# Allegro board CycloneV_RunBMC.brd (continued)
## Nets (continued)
P3V3_AUX_M10_VCCIO1A: CB86.1 CB88.1 CB97.1 FBB2.2(B) UT4.G4 UT4.H4
P3V3_AUX_SPI: CB14.1 CB18.1 CRB1.1(C) EUB1.8 RB18.1 RB29.1 RB35.1 RB38.1 TP1.1(TP)
P3V3_SI5338_AUX: C5C1.1 C5C2.1 C5C7.1 C5C8.1 C5C13.1 C5N17.1 CB199.1 CB201.1 CB209.1 CB212.1 EU5C1.10 EU5C1.11 EU5C1.14 EU5C1.18 EU5C1.20 FB5C1.2(B)
P3V3_USBPHY_AUX: C2L16.1 C2L17.1 C2L18.1 R2L48.2(B) R8A64.1 U8A6.8 U8A6.11 U8A6.14 U8A6.32
P3V3_USBPHY_OUT_AUX: C7A14.1 C7A15.1 U8A6.20
P3V3_USBPHY_USB2B_AUX: C316.1 C317.1 C318.1 EU12.8 EU12.11 EU12.14 EU12.32 R410.1 R414.2(B)
P3V3_USBPHY_USB2B_OUT_AUX: C319.1 C320.1 EU12.20
P5V_AUX: FB11.1 R391.2(B) R392.1
P5V_AUX_PIN140: JT3.140 R391.1
P5V_AUX_USB2A_VSENSE: JT3.211 R392.2(B)
P5V_USBPHY_AUX: C3L11.1 CB206.1 CB207.1 FB11.2(B) R7A52.1
P5V_USBPHY_USB2B_AUX: C305.1 C321.1 C322.1 FB17.2(B) R395.1
P5V_USBPHY_USB2B_VSENSE: FB17.1 JT3.209
P12V_AUX: FBB7.1 FBB11.1 RB171.1 RT116.2(B)
P12V_AUX_EDGE: JT3.1 RT116.1 RT134.1
PVCCIO_CPU0: CB213.1 RT113.1 U8.2
PVCCIO_CPU0_CONN: JT3.111 RT113.2(B)
A_BMC_ADC4: CT11.1 JT3.182 UT4.G2
A_EMMC_VDDIM_DECAP: CT3.1 CT5.1 UB4.E4
A_P1V05_PCH_AUX_SENSE: CB96.1 JT3.180 UT4.G5
A_P1V8_PCH_AUX_SENSE: CT16.1 JT3.186 UT4.E1
A_P3V3_SCALED_SENSE: CT12.1 JT3.176 UT4.F4
A_P3V_BAT_SENSE: CT17.1 JT3.188 UT4.D1
A_P5V_AUX_SCALED_SENSE: CT15.1 JT3.184 UT4.F1
A_P12V_SCALED_SENSE: CB103.1 JT3.174 UT4.F5
A_PVCCIN_CPU0_SCALED: CT22.1 JT3.252 UT4.C4
A_PVCCIN_CPU1_SCALED: CT18.1 JT3.254 UT4.C1
A_PVCCIO_CPU0_SENSOR: CT20.1 JT3.260 UT4.B1
A_PVDDQ_ABC_CPU0_SENSOR: CB120.1 JT3.256 UT4.E3
A_PVDDQ_ABC_CPU1_SENSOR: CT19.1 JT3.258 UT4.C2
A_PVDDQ_DEF_CPU0_SENSOR: CT13.1 JT3.255 UT4.F2
A_PVDDQ_DEF_CPU1_SENSOR: CT21.1 JT3.257 UT4.B2
A_PVMCP_CPU0_SENSOR: CB143.1 JT3.259 UT4.C3
A_PVNN_PCH_AUX_SENSE: CB91.1 JT3.178 UT4.H5
A_USBPHY_PCH_VBUS: R7A52.2(B) U8A6.22
A_USBPHY_USB2B_VBUS: EU12.22 R395.2(B)
CLK_25M_HPS_CLK1: RT118.2(B) UT7.E20
CLK_25M_HPS_CLK1_R: EU5C1.13 RT118.1
CLK_25M_HPS_CLK2: RT117.2(B) UT7.D20
CLK_25M_HPS_CLK2_R: EU5C1.12 RT117.1
CLK_25M_M10: R5N6.2(B) UT4.J11
CLK_25M_M10_R: EU5C1.8 R5N6.1
CLK_50M_C5_FPGA: RT102.2(B) UT7.V11
CLK_50M_C5_FPGA_R: EU5C1.9 RT102.1
CLK_50M_CKMNG_BMCB: JT3.220 UT7.V12
CLK_100M_BMC_PE_DN: JT3.159 UT7.V4
CLK_100M_BMC_PE_DP: JT3.161 UT7.V5
DBG_RSMRST_MONITOR_N: JT3.103 UT4.K6
DBG_XDP_SYSPWROK_HOOK3: JT3.119 UT7.W11
DBP_DEBUG_EN_N: JT3.89 RB130.2(B) UT7.AD10
DBP_JUMPER_EN_DET: JT3.99 UT7.T11
DBP_PRDY_N: JT3.83 UT7.AF4
DBP_PREQ_N: JT3.85 RB131.2(B) UT7.AE9
DBP_PWR_DEBUG_HOOK2_N: JT3.87 RT112.2(B) UT7.AE4
DBP_SMC_NTRST_N: JT3.162 UT7.AE7
DBP_SMC_TCK: JT3.170 RB134.2(B)
DBP_SMC_TCK_R: RB134.1 UT7.AE8
DBP_SMC_TDI: JT3.166 RB125.2(B)
DBP_SMC_TDI_R: RB125.1 UT7.AE11
DBP_SMC_TDO: JT3.164 UT7.AF9
DBP_SMC_TMS: JT3.172 RB122.2(B)
DBP_SMC_TMS_R: RB122.1 UT7.AD11
DBP_TCK_MUX_SEL: JT3.95 UT7.AF8
DBP_XDP_PRSNT_N: JT3.91 UT7.U11
EMMC_SMC_CLK: RT38.1 RT46.1 RT138.2(B) UT7.AD26
EMMC_SMC_CLK_CONN: JT1.10 RT138.1
EMMC_SMC_CLK_R: RT38.2(B) UB4.P6
EMMC_SMC_CMD: RB34.1 RT40.1 RT140.2(B) UT7.AF26
EMMC_SMC_CMD_CONN: JT1.14 RT140.1
EMMC_SMC_CMD_R: RT40.2(B) UB4.P5
EMMC_SMC_DAT0: RB25.1 RT16.1 RT139.2(B) UT7.AE26
EMMC_SMC_DAT0_CONN: JT1.12 RT139.1
EMMC_SMC_DAT0_R: RT16.2(B) UB4.K2
EMMC_SMC_DAT1: RB84.1 RB143.1 UT7.Y19
EMMC_SMC_DAT1_R: RB84.2(B) UB4.N2
EMMC_SMC_DAT2: RT11.1 RT15.1 UT7.AE25
EMMC_SMC_DAT2_R: RT15.2(B) UB4.K3
EMMC_SMC_DAT3: RT41.1 RT43.1 UT7.Y17
EMMC_SMC_DAT3_R: RT41.2(B) UB4.N3
EMMC_SMC_DAT4: RT21.1 RT27.1 UT7.Y18
EMMC_SMC_DAT4_R: RT27.2(B) UB4.N8
EMMC_SMC_DAT5: RT18.1 RT98.1 UT7.AB23
EMMC_SMC_DAT5_R: RT18.2(B) UB4.K8
EMMC_SMC_DAT6: RT30.1 RT36.1 UT7.AA24
EMMC_SMC_DAT6_R: RT30.2(B) UB4.N9
EMMC_SMC_DAT7: RT13.1 RT99.1 UT7.V16
EMMC_SMC_DAT7_R: RT13.2(B) UB4.K9
EMMC_STRB_R: RT14.1 UB4.K5
FAN_PWM0: EUT3.20 JT3.26
FAN_PWM1: EUT3.18 JT3.28
FAN_PWM2: EUT3.16 JT3.27
FAN_PWM3: EUT3.14 JT3.30
FAN_PWM4: EUT3.12 JT3.29
FAN_PWM5: EUT3.10 JT3.32
FAN_TACH0: EUT3.19 JT3.78
FAN_TACH1: EUT3.17 JT3.80
FAN_TACH2: EUT3.15 JT3.82
FAN_TACH3: EUT3.13 JT3.84
FAN_TACH4: EUT3.11 JT3.86
FAN_TACH5: EUT3.9 JT3.88
FM_B2B_BUFFER_OE3_N: JT3.146 UT4.B12
FM_B2B_BUFFER_OE4_N: JT3.144 UT4.B11
FM_BIOS_POST_CMPLT_N: JT3.68 UT7.A18
FM_BMC_HBIN: JT3.141 UT7.E8
FM_BMC_HBOUT: JT3.143 UT7.D8
FM_BMC_ON: JT3.109 UT4.F10
FM_BMC_ONCTL_R_N: JT3.36 RB82.2(B) UT7.H16
FM_BMC_PWRBTN_OUT_N: JT3.40 RT108.2(B) UT7.AG6
FM_BOARD_ID: JT3.201 RB86.1 UT4.F12
FM_C5_BSEL0: RB79.2(B) UT7.J17
FM_C5_BSEL1: RT20.1 UT7.A6
FM_C5_BSEL2: RT78.1 UT7.D15
FM_C5_CONF_DONE: RT28.1 UT4.M15 UT7.J8
FM_C5_CONFIG_N: RB71.1 UT4.L12 UT7.F7
FM_C5_DEV_OE_N: RB75.1 UT7.AC24
FM_C5_FPGA_AS_DATA0: RB69.2(B) UT7.AD7
FM_C5_FPGA_AS_DATA0_R: RB69.1 UT4.M14
FM_C5_FPGA_DCLK: RB135.1 RT37.2(B) UT7.AA8
FM_C5_FPGA_DCLK_R: RT37.1 UT4.L16
FM_C5_FPGA_MSEL0: RT84.2(B) RT85.1 UT4.A2 UT7.J10
FM_C5_FPGA_MSEL1: RT73.2(B) RT83.1 UT4.A3 UT7.H9
FM_C5_FPGA_MSEL2: RT75.1 RT76.2(B) UT4.A4 UT7.G6
FM_C5_FPGA_MSEL3: RT81.1 RT82.2(B) UT4.A5 UT7.K10
FM_C5_FPGA_MSEL4: RT79.2(B) RT80.1 UT4.A6 UT7.K9
FM_C5_INIT_DONE: RT87.2(B) UT4.A8 UT7.AA20
FM_C5_M10_RSVD<0>: UT4.L9 UT7.AB26
FM_C5_M10_RSVD<1>: UT4.L10 UT7.W20
FM_C5_M10_RSVD<2>: UT4.M10 UT7.AA26
FM_C5_M10_RSVD<3>: UT4.M11 UT7.Y24
FM_C5_STATUS_N: RT34.1 UT4.L15 UT7.H8
FM_CPLD_HOLD_N: JT3.131 RT123.2(B) UT7.AC23
FM_CPU_BMC_MSMI_CATERR_LVT3_N: JT3.37 UT7.H17
FM_CPU_BMCINIT: JT3.195 UT7.AH22
FM_CPU_ERR2_LVT3_N: JT3.79 UT7.A7
FM_DEDI_IO3: RB18.2(B) RB101.1 TP8.1(TP)
FM_DS1818_EN: CB1.1 Q3L1.3 Q6A1.2(VCC) Q7A1.2(VCC) RB31.2(B)
FM_DS1818_EN_G: Q3L1.5 Q3L1.6 R3L1.2(B)
FM_DUMP_ALERT_N: JT3.25 RT71.2(B) UT4.A12
FM_EXT_PWR_MODE: JT3.118 UT7.AF22
FM_FAN0_PRSNT_N: EUT1.1 JT3.94
FM_FAN1_PRSNT_N: EUT1.2 JT3.96
FM_FAN2_PRSNT_N: EUT1.3 JT3.98
FM_FAN3_PRSNT_N: EUT1.4 JT3.100
FM_FAN4_PRSNT_N: EUT1.5 JT3.102
FM_FAN5_PRSNT_N: EUT1.6 JT3.104
FM_FAN6_PRSNT_N: EUT1.7 JT3.106
FM_FAN7_PRSNT_N: EUT1.8 JT3.108
FM_FORCE_BMC_UPDATE_N: JT3.105 UT7.AE24
FM_FRU_A2: RB86.2(B) RB94.1 UB5.3
FM_HPS_PORSEL: RB89.1 RB99.2(B) UT7.E18
FM_IM_MASTER: JT3.115 UT4.F11
FM_JTAG_MUX_SEL: RT24.2(B) ST1.4(IO4) U12.1 UB2.6 UB3.6
FM_JTAG_MUX_SEL_SW: RT60.2(B) ST1.2
FM_LED_AMBER_GATE: QB1.2 RT42.1 UT4.K2
FM_LED_BEEP_BMC: JT3.129 UT7.AF6
FM_LED_GREEN_GATE: QB1.5 RB68.1 UT4.K5
FM_M10_CONFIG_SEL: RB85.1 RB87.2(B) UT4.F8
FM_M10_DEBUG_0: JT1.9(IO9) UT4.R11 UT7.W21
FM_M10_DEBUG_1: JT1.11 UT4.R12 UT7.AA23
FM_M10_DEBUG_2: JT1.13 UT4.T12 UT7.V15
FM_M10_DEV_CLR_N: RB101.2(B) UT4.B10
FM_M10_EDGE_RSVD<2>: JT3.148 UT4.L1
FM_M10_EDGE_RSVD<3>: JT3.150 UT4.L2
FM_M10_EDGE_RSVD<4>: JT3.190 UT4.L3
FM_M10_EDGE_RSVD<5>: JT3.192 UT4.M3
FM_M10_EDGE_RSVD<6>: JT3.194 UT4.L6
FM_M10_EDGE_RSVD<7>: JT3.196 UT4.M2
FM_M10_JTAGEN: RT25.1 ST1.3 UT4.G6
FM_M10_JTAGEN_SW: RT58.2(B) ST1.1
FM_P0V75_AUX_EN_R: C8F8.1 EU8F1.7 R8F8.2(B)
FM_P3V3_AUX_IO_G: CT14.1 RT50.2(B) UT3.3
FM_PCH_BMC_THERMTRIP_N: JT3.35 UT7.A17
FM_PGPPA_AUX_IO_G: CT10.1 RT39.2(B) UT2.3
FM_PVCCIN_CPU0_PWR_IN_ALERT_N: JT3.72 UT7.AH21
FM_PVCCIN_CPU1_PWR_IN_ALERT_N: JT3.117 UT7.AD23
FM_SI5338_SMB_A0: EU5C1.3 R5C13.1
FM_SKT0_FAULT_LED: JT3.38 UT4.K15
FM_SLPS4_N: JT3.138 UT7.AE23
FM_SW_ON: JT3.107 UT4.E11
FM_TPM_EN_PULSE: JT3.93 UT7.AH4
FM_USB2A_PWREN: JT3.213 R390.2(B)
FM_USBPHY_PCH_CPEN: R390.1 U8A6.17
FM_USBPHY_PCH_ID: R7A54.2(B) U8A6.23
FM_USBPHY_USB2B_CPEN: EU12.17 R412.1
FM_USBPHY_USB2B_ID: EU12.23 R396.2(B)
FM_VGA_B<0>: R424.1 UT7.AG19
FM_VGA_B<1>: R420.1 UT7.AD20
FM_VGA_B<2>: R423.1 UT7.AH19
FM_VGA_B<3>: R417.1 UT7.AG18
FM_VGA_G<0>: R428.1 UT7.AA19
FM_VGA_G<1>: R422.1 UT7.AH18
FM_VGA_G<2>: R427.1 UT7.AA18
FM_VGA_G<3>: R419.1 UT7.AE19
FM_VGA_R<0>: R426.1 UT7.AF18
FM_VGA_R<1>: R421.1 UT7.AD19
FM_VGA_R<2>: R425.1 UT7.AH17
FM_VGA_R<3>: R418.1 UT7.Y15
FP_ID_BTN_N: JT3.199 UT7.T12
FP_ID_LED_N: JT3.122 RB179.2(B) UT7.AH2
FP_LED_STATUS_AMBER_N: JT3.124 RB182.2(B) UT7.T13
FP_LED_STATUS_GREEN_N: JT3.158 RB154.2(B) UT7.AH3
FP_NMI_BTN_N: JT3.193 UT7.AF11
FP_PWR_BTN_N: JT3.160 UT7.AF5
FP_RST_BTN_N: JT3.121 UT7.AF10
IRQ_BMC_PCH_NMI: JT3.42 UT7.C14
IRQ_BMC_PCH_SCI_LPC_R_N: JT3.44 RB73.2(B) UT7.J16
IRQ_BMC_PCH_SMI_LPC_N: JT3.154 RB72.2(B) UT7.AF23
IRQ_L_PIRQA_N_E_ALERT0_N_BMC: JT3.171 UT7.AA4
IRQ_NMI_EVENT_N: JT3.46 UT7.B14
IRQ_SMB_INTERNAL_ALERT_N: RB88.1 RB140.1 UT7.C17
IRQ_SMB_INTERNAL_ALERT_R_N: EUT1.22 EUT2.6 RB140.2(B)
IRQ_SMI_ACTIVE_N: JT3.70 UT7.AG24
IRQ_SML0_ALERT_N: JT3.66 RB95.1 UT7.B18
IRQ_SML1_PMBUS_ALERT_N: JT3.74 RT57.1 UT7.AG15
ISENSE_P3V3_C: CB210.1 RB161.2(B)
ISENSE_P3V3_N: EUT2.5 RT101.2(B)
ISENSE_P3V3_P: CB210.2(B) EUT2.4
ISENSE_P12V_C: CT25.1 RT134.2(B)
ISENSE_P12V_N: EUT2.1 RB171.2(B)
ISENSE_P12V_P: CT25.2(B) EUT2.16
JTAG_C5_FPGA_TCK: CB22.1 RB48.1 U12.4 UT7.AB5
JTAG_C5_FPGA_TDI: CB33.1 RB49.2(B) U12.9 UT7.W10
JTAG_C5_FPGA_TDO: CT7.1 RB123.1 U12.12
JTAG_C5_FPGA_TDO_R: RB123.2(B) UT7.Y9
JTAG_C5_FPGA_TDO_SW: U12.14 UB2.3
JTAG_C5_FPGA_TMS: CB23.1 RB46.2(B) U12.7 UT7.AC7
JTAG_HDR_SW_TCK: RB52.2(B) U12.2
JTAG_HDR_SW_TMS: RB26.2(B) U12.5
JTAG_HDR_TCK: J8.1 RB51.1 RB52.1
JTAG_HDR_TDI: J8.9(IO9) RB22.1
JTAG_HDR_TDO: CB51.1 J8.3 UB2.4
JTAG_HDR_TMS: J8.5 RB26.1 RB28.1
JTAG_HPS_TCK: J4.4 RT1.1 UT7.K19
JTAG_HPS_TDI: J4.8 RT3.2(B) UT7.D22
JTAG_HPS_TDO: J4.6 RT4.2(B) UT7.B23
JTAG_HPS_TMS: J4.2 RT5.2(B) UT7.C23
JTAG_M10_MASTER_TCK: RB54.2(B) U12.3
JTAG_M10_MASTER_TCK_R: RB54.1 UT4.K11
JTAG_M10_MASTER_TDI: RB70.2(B) U12.10
JTAG_M10_MASTER_TDI_R: RB70.1 UT4.K14
JTAG_M10_MASTER_TDO: U12.13 UT4.L11
JTAG_M10_MASTER_TMS: RB55.2(B) U12.6
JTAG_M10_MASTER_TMS_R: RB55.1 UT4.K12
JTAG_M10_TCK: CB55.1 RB51.2(B) RB53.1 UT4.H3
JTAG_M10_TDI: CB2.1 RB22.2(B) RB24.2(B) UT4.G1
JTAG_M10_TDO: RT48.2(B) UB3.4
JTAG_M10_TDO_BYPASS: UB2.1 UB3.1
JTAG_M10_TDO_R: RT48.1 UT4.H1
JTAG_M10_TDO_SW: U12.11 UB3.3
JTAG_M10_TMS: CB17.1 RB28.2(B) RB33.2(B) UT4.H2
LED_AMBER_C: DST2.C RT32.1
LED_AMBER_R: QB1.6 RT32.2(B)
LED_GREEN_C: DST1.2(C) RT31.1
LED_GREEN_R: QB1.3 RT31.2(B)
LPC_CLK_24M_66M_LPC0_ESPI_BMC: JT3.179 UT7.U9
LPC_LAD0_ESPI_IO0_BMC: JT3.169 UT7.W8
LPC_LAD1_ESPI_IO1_BMC: JT3.167 UT7.Y4
LPC_LAD2_ESPI_IO2_BMC: JT3.177 UT7.AB4
LPC_LAD3_ESPI_IO3_BMC: JT3.175 UT7.T8
LPC_LFRAME_N_ESPI_CS0_N_BMC: JT3.173 UT7.Y5
NC_EMMC<0>: UB4.A1
NC_EMMC<1>: UB4.A2
NC_EMMC<2>: UB4.A9
NC_EMMC<3>: UB4.A10
NC_EMMC<4>: UB4.B1
NC_EMMC<5>: UB4.B10
NC_EMMC<6>: UB4.T1
NC_EMMC<7>: UB4.T10
NC_EMMC<8>: UB4.U1
NC_EMMC<9>: UB4.U2
NC_EMMC<10>: UB4.U9
NC_EMMC<11>: UB4.U10
NC_EMMC_RFU<0>: UB4.D2
NC_EMMC_RFU<1>: UB4.D3
NC_EMMC_RFU<2>: UB4.D4
NC_EMMC_RFU<3>: UB4.D5
NC_EMMC_RFU<4>: UB4.D6
NC_EMMC_RFU<5>: UB4.D7
NC_EMMC_RFU<6>: UB4.D8
NC_EMMC_RFU<7>: UB4.D9
NC_EMMC_RFU<8>: UB4.E2
NC_EMMC_RFU<9>: UB4.E3
NC_EMMC_RFU<10>: UB4.E5
NC_EMMC_RFU<11>: UB4.E6
NC_EMMC_RFU<12>: UB4.E7
NC_EMMC_RFU<13>: UB4.E8
NC_EMMC_RFU<14>: UB4.E9
NC_EMMC_RFU<15>: UB4.H4
NC_EMMC_RFU<16>: UB4.H5
NC_EMMC_RFU<17>: UB4.H6
NC_EMMC_RFU<18>: UB4.H7
NC_EMMC_RFU<19>: UB4.J2
NC_EMMC_RFU<20>: UB4.J3
NC_EMMC_RFU<21>: UB4.J4
NC_EMMC_RFU<22>: UB4.J6
NC_EMMC_RFU<23>: UB4.J7
NC_EMMC_RFU<24>: UB4.J8
NC_EMMC_RFU<25>: UB4.J9
NC_EMMC_RFU<26>: UB4.K4
NC_EMMC_RFU<27>: UB4.K6
NC_EMMC_RFU<28>: UB4.K7
NC_EMMC_RFU<29>: UB4.L5
NC_EMMC_RFU<30>: UB4.L6
NC_EMMC_RFU<31>: UB4.M2
NC_EMMC_RFU<32>: UB4.M3
NC_EMMC_RFU<33>: UB4.M6
NC_EMMC_RFU<34>: UB4.M8
NC_EMMC_RFU<35>: UB4.M9
NC_EMMC_RFU<36>: UB4.N4
NC_EMMC_RFU<37>: UB4.N5
NC_EMMC_RFU<38>: UB4.N6
NC_EMMC_RFU<39>: UB4.N7
NC_EMMC_RFU<40>: UB4.P4
NC_EMMC_RFU<41>: UB4.P7
NC_FAN_PWM_START0: EUT3.25 RB149.2(B) RB150.1
NC_JTAG_FPGA_P6: J8.6
NC_JTAG_FPGA_P8: J8.8
NC_JTAG_HDR_P7: J8.7
NC_M10_VREFB7: UT4.A15
NC_M10_VREFB8: UT4.A9
NC_MAX_XTAL2: EUT3.6(XTAL2)
NC_USBPHY_PCH_NC: U8A6.12
NC_USBPHY_PCH_SPK_L: U8A6.15
NC_USBPHY_PCH_SPK_R: U8A6.16
NC_USBPHY_USB2B_NC: EU12.12
NC_USBPHY_USB2B_SPK_L: EU12.15
NC_USBPHY_USB2B_SPK_R: EU12.16
NL_C5_M10_RX_CLK: UT4.P14 UT7.AH24
NL_C5_M10_RX_DAT: UT4.P15 UT7.AG26
NL_C5_M10_TX_CLK: UT4.N14 UT7.AH23
NL_C5_M10_TX_DAT: UT4.N16 UT7.AG23
P2E_PCH_BMC_RX_C_DN: CT30.1 UT7.AD1
P2E_PCH_BMC_RX_C_DP: CT29.1 UT7.AD2
P2E_PCH_BMC_RX_DN: CT30.2(B) JT3.153
P2E_PCH_BMC_RX_DP: CT29.2(B) JT3.155
P2E_PCH_BMC_TX_DN: JT3.147 UT7.AF1
P2E_PCH_BMC_TX_DP: JT3.149 UT7.AF2
PD_BMC_DDR3_DQS5_P: RB56.1 U4.C7
PD_C5_RREF_TL: RB167.2(B) UT7.B1
PD_CLK_50OHM_TERM: JT3.116 RB187.1
PD_FAN_FREQ_START: EUT3.1 RB146.1 RB147.2(B)
PD_FAN_PWM_START1: EUT3.26 RB144.2(B) RB151.1
PD_FAN_SPIN_START: EUT3.2 RB152.1 RB153.2(B)
PD_FRU_A1: R1A11.1 UB5.2
PD_HPS_RZQ_0: RB74.1 UT7.D25
PD_PCA9554_A0: EUT1.18 RB132.1
PD_PCA9554_A1: EUT1.23 RB137.1
PD_PCA9554_A2: EUT1.24 RB136.1
PD_QS3VH257QG_OE_N: RT10.1 U12.15
PD_SI5351_EN_N: EU5C1.7 R5C8.1
PD_SI5351_SSEN: EU5C1.6 R5C14.1
PD_SPI_EEPROM_WP: R2A17.2(B) R436.1 UB5.7(WP)
PD_TELEMETRY_ADDR: EUT2.14 RB145.1
PD_USBPHY_PCH_RBIAS: R7A55.1 U8A6.24
PD_USBPHY_USB2B_RBIAS: EU12.24 R397.1
PD_V_M_DDR3_DQU<0>: RB63.1 U4.D7
PD_V_M_DDR3_DQU<1>: RB61.1 U4.C3
PD_V_M_DDR3_DQU<2>: RB65.1 U4.C8
PD_V_M_DDR3_DQU<3>: RB59.1 U4.C2
PD_V_M_DDR3_DQU<4>: RB62.1 U4.A7
PD_V_M_DDR3_DQU<5>: RB58.1 U4.A2
PD_V_M_DDR3_DQU<6>: RB64.1 U4.B8
PD_V_M_DDR3_DQU<7>: RB60.1 U4.A3
PECI_SMC: JT3.112 RB180.1 RB181.2(B)
PECI_SMC_IN: RB90.1 U7.3
PECI_SMC_IN_LVC33: RB77.2(B) UT7.AH16
PECI_SMC_OUT_B: RB168.1 U8.4
PECI_SMC_OUT_N: RT115.1 UT7.AA15
PECI_SMC_OUT_N_R1: RB169.2(B) RT115.2(B) U8.1(OE_N)
PECI_SMC_R: RB77.1 U7.4
PECI_SMC_S_R: RB90.2(B) RB168.2(B) RB181.1
PU_BATTERY_SENSE_EN: JT3.156 RB178.2(B)
PU_BMC_DDR3_DQS5_N: RB57.2(B) U4.B7
PU_FAN_MAX_A0: EUT3.4 RB163.1 RB164.2(B)
PU_FAN_MAX_A1: EUT3.3 RB159.1 RB160.2(B)
PU_FAN_PWM6: JT3.31 RT122.2(B)
PU_FAN_PWM7: JT3.34 RB185.2(B)
PU_FAN_WD_START: EUT3.5 RB165.1 RB166.2(B)
PU_FRU_A0: R1A9.1 UB5.1
PU_JTAG_HPS_TRST_N: RB78.2(B) UT7.C22
PU_M10_CONF_DONE: RB96.1 UT4.E7
PU_M10_CONFIG_N: RB97.1 UT4.E8
PU_M10_STATUS_N: RB91.1 UT4.F7
PU_MAX_FSD_N: EUT3.27 R393.2(B)
PU_P1V1_AUX_EN: RT63.2(B) RT67.1
PU_P1V2_AUX_EN: RB127.2(B) RB128.1
PU_P1V8_AUX_EN: RB141.1 RB142.2(B)
PU_TELEMETRY_ENA: EUT2.11 RT94.2(B)
PU_TELEMETRY_SHTDN: EUT2.10 RT96.2(B)
PU_TMP75_8_A0: RT103.1 RT109.2(B) UT10.7
PU_TMP75_8_A1: RT104.1 RT105.2(B) UT10.6
PU_TMP75_8_A2: RT130.1 RT131.2(B) UT10.5
PU_TRACE_GND_DETECT: J4.9(IO9) RB27.2(B)
PU_V_M_BMC_DDR3_DM_5: RB50.2(B) U4.D3
PWRGD_BMC_AUX_VRS: JT3.81 R8F12.2(B) R8L2.1
PWRGD_CPU0_LVC3: JT3.120 UT7.AG20
PWRGD_P0V75_AUX_R: C8F7.1 EU8F1.9 R8F7.2(B) R8F12.1
PWRGD_P1V1_AUX: QT1.5 RT51.1 RT53.2(B) RT62.1 UT6.12
PWRGD_P1V1_AUX_N: QT1.3 RT39.1 RT45.2(B) RT50.1
PWRGD_P1V5_AUX: R8F8.1 RT52.2(B) UT5.12
PWRGD_P1V8_PCH_AUX: JT3.59 UT4.J14
PWRGD_P2V5_AUX: RT61.2(B) UT8.12
PWRGD_PS_PWROK_PLD_BMC: JT3.77 UT7.A8
PWRGD_SMC_AUX_VRS_R2: Q3L1.2 R8L2.2(B)
RGMII_BMC_RMM4_MDC: JT3.246 RB189.1 RT74.1
RGMII_BMC_RMM4_MDIO: JT3.248 RB103.1 RB188.1
RGMII_BMC_RMM4_R_MDC: RT74.2(B) UT7.A13
RGMII_BMC_RMM4_R_MDIO: RB103.2(B) UT7.E16
RGMII_BMC_RMM4_R_TXD_0: RT128.2(B) UT7.A16
RGMII_BMC_RMM4_R_TXD_1: RT133.2(B) UT7.J14
RGMII_BMC_RMM4_R_TXD_2: RT129.2(B) UT7.A15
RGMII_BMC_RMM4_R_TXD_3: RT132.2(B) UT7.D17
RGMII_BMC_RMM4_RX_CLK: JT3.250 UT7.J12
RGMII_BMC_RMM4_RX_CTRL: JT3.242 UT7.J13
RGMII_BMC_RMM4_RXD_0: JT3.231 UT7.A14
RGMII_BMC_RMM4_RXD_1: JT3.235 UT7.A11
RGMII_BMC_RMM4_RXD_2: JT3.243 UT7.C15
RGMII_BMC_RMM4_RXD_3: JT3.247 UT7.A9
RGMII_BMC_RMM4_TX_CLK: JT3.240 RB186.1
RGMII_BMC_RMM4_TX_CTRL: JT3.244 RB183.1
RGMII_BMC_RMM4_TX_R_CLK: RB186.2(B) UT7.J15
RGMII_BMC_RMM4_TX_R_CTRL: RB183.2(B) UT7.A12
RGMII_BMC_RMM4_TXD_0: JT3.229 RT128.1
RGMII_BMC_RMM4_TXD_1: JT3.237 RT133.1
RGMII_BMC_RMM4_TXD_2: JT3.241 RT129.1
RGMII_BMC_RMM4_TXD_3: JT3.249 RT132.1
RMII_BMC_NIC_TX_EN: JT3.224 RB184.2(B)
RMII_BMC_NIC_TX_R_EN: RB184.1 UT7.AH5
RMII_BMC_NIC_TXD_0: JT3.234 RB119.2(B)
RMII_BMC_NIC_TXD_0_R: RB119.1 UT7.AE12
RMII_BMC_NIC_TXD_1: JT3.236 RB112.2(B)
RMII_BMC_NIC_TXD_1_R: RB112.1 UT7.W12
RMII_NIC_BMC_CRS_DV: RB191.2(B) UT7.AH6
RMII_NIC_BMC_CRS_R_DV: JT3.216 RB191.1
RMII_NIC_BMC_RXD_0: RB173.2(B) UT7.AD12
RMII_NIC_BMC_RXD_1: RB172.2(B) UT7.AG5
RMII_NIC_BMC_RXD_R_0: JT3.228 RB173.1
RMII_NIC_BMC_RXD_R_1: JT3.230 RB172.1
RST_BMC_RSTBTN_OUT_N: JT3.76 RB139.2(B) UT7.AF7
RST_EMMC_SMC_R_N: RT12.2(B) UB4.M5
RST_ESPI_RESET_BMC_N: JT3.165 UT7.Y8
RST_HPS_POR_M10_N: R4L128.2(B) UT1.3 UT4.A11
RST_HPS_POR_N: JT1.7 R4L29.2(B) R4L39.2(B) R4L40.2(B) UT7.H19
RST_HPS_POR_R1_N: R4L29.1 UT1.4(2Y)
RST_HPS_POR_R_N: R4L39.1 UT1.6
RST_HPS_PORBTN__R_N: Q6A1.1 R4L38.2(B) S7A2.2(B) UT1.1
RST_HPS_RST_M10_N: RB21.2(B) UB1.3 UT4.A10
RST_HPS_RST_N: J4.10 R7A2.2(B) R7A4.2(B) RB36.2(B) RT12.1 UT7.A23
RST_HPS_RST_R1_N: R7A2.1 UB1.6
RST_HPS_RST_R2_N: RB36.1 UB1.4(2Y)
RST_HPS_RSTBTN__R_N: Q7A1.1 R7A1.2(B) S7A1.2(B) UB1.1
RST_PERSTL1_R: RB177.1 UT7.W15
RST_PLTRST_B_N: JT3.142 RB175.2(B) RB177.2(B)
RST_PLTRST_MONITOR_N: JT3.97 UT7.AF21
RST_SMC_SMB_MUX_RST_N: JT3.101 RT59.1 UT7.AH14
RST_USBPHY_RESET_N: RT91.2(B) U8A6.27 UT7.C6
RST_USBPHY_USB2B_RESET_N: EU12.27 R411.2(B) UT7.E4
SGPIO_SMC_CPLD_CLK: JT3.19 UT7.AF27
SGPIO_SMC_CPLD_DIN: JT3.15 UT7.AF25
SGPIO_SMC_CPLD_DOUT: JT3.17 UT7.AF28
SGPIO_SMC_CPLD_LD_N: JT3.13 UT7.AG28
SMB_BATPAK_CLK: JT3.187 RT33.1 UT7.AH26
SMB_BATPAK_DATA: JT3.189 RT137.1 UT7.AC22
SMB_BMC2BMC_CLK: JT3.181 R2A21.1 RB148.1 UT7.AG16
SMB_BMC2BMC_DATA: JT3.183 R2A22.2(B) RT70.1 UT7.AH12
SMB_BMC_RSSD_7_0_CLK: JT3.123 RT93.1 UT7.AG8
SMB_BMC_RSSD_7_0_DATA: JT3.125 RT114.1 UT7.AG13
SMB_C5_M10_CLK: RT49.1 RT68.2(B) UT4.H15
SMB_C5_M10_DATA: RT44.2(B) RT47.1 UT4.H16
SMB_C5_M10_R_CLK: RT68.1 UT7.AH13
SMB_C5_M10_R_DATA: RT44.1 UT7.W14
SMB_HOST_LVC3_CLK: JT3.134 RB190.1 UT7.U14
SMB_HOST_LVC3_DATA: JT3.136 RT90.1 UT7.AG9
SMB_HSBP_LVC3_CLK: JT3.60 RT88.1 UT7.AH9
SMB_HSBP_LVC3_DATA: JT3.62 RB106.1 UT7.AE15
SMB_INTERNAL_CLK: EUT1.19 EUT2.3 EUT3.23 JT1.5 R434.1 RB98.2(B) RT92.1
SMB_INTERNAL_CLK_R2: EU5C1.4 R434.2(B)
SMB_INTERNAL_DATA: EUT1.20 EUT2.2 EUT3.22 JT1.6 R435.1 RT95.2(B) RT97.1
SMB_INTERNAL_DATA_R2: EU5C1.5 R435.2(B)
SMB_INTERNAL_R_CLK: RB98.1 UT7.AF17
SMB_INTERNAL_R_DATA: RT95.1 UT7.V13
SMB_IPMB_LVC3_CLK: JT3.128 RB138.1 UT7.AH7
SMB_IPMB_LVC3_DATA: JT3.130 RB116.1 UT7.AF13
SMB_PCIE_LVC3_CLK: JT3.205 RB102.1 UT7.U13
SMB_PCIE_LVC3_DATA: JT3.207 RB133.1 UT7.AH8
SMB_PMBUS_LVC3_CLK: JT3.47 RB104.1 UT7.Y13
SMB_PMBUS_LVC3_DATA: JT3.49 RT72.1 UT7.AG11
SMB_RSSD_15_8_CLK: JT3.50 RT23.1 UT7.AH27
SMB_RSSD_15_8_DATA: JT3.48 RT35.1 UT7.AG25
SMB_SENSOR_FRU_CLK: R2A21.2(B) UB5.6
SMB_SENSOR_FRU_DAT: R2A22.1 UB5.5
SMB_SMLINK0_LVC3_CLK: JT3.54 RT86.1 UT7.AG10
SMB_SMLINK0_LVC3_DATA: JT3.56 RB109.1 UT7.AF15
SMB_SW2BMC_CLK_DBG_HOOK8: JT3.135 RT135.1 UT7.D12
SMB_SW2BMC_DATA_DBG_HOOK9: JT3.137 RT136.1 UT7.C12
SMB_TEMP_SENSOR_LVC3_CLK: JT3.53 RB105.1 UT7.AA13 UT10.2
SMB_TEMP_SENSOR_LVC3_DATA: JT3.55 RT89.1 UT7.AH11 UT10.1
SP_BMC_UART0_RXD: JT1.2 JT3.21 RT106.2(B) UT7.B19
SP_BMC_UART0_TXD: JT1.1 JT3.23 RT107.2(B) UT7.C16
SP_BMC_UART1_RXD: JT1.4 JT3.41 RB158.2(B) UT7.C19
SP_BMC_UART1_TXD: JT1.3 JT3.43 RT100.2(B) UT7.B16
SPI_M10_FLASH_CLK: EUB1.6 RB111.1 TP4.1(TP)
SPI_M10_FLASH_CLK_R: RB111.2(B) UT4.B4
SPI_M10_FLASH_CS0__RN: RB107.2(B) UT4.B3
SPI_M10_FLASH_CS0_N: EUB1.1 RB38.2(B) RB107.1 TP3.1(TP)
SPI_M10_FLASH_IO2_WP_N: EUB1.3(WP_N_SIO2) RB29.2(B) RB110.1
SPI_M10_FLASH_IO2_WP_R_N: RB110.2(B) UT4.B7
SPI_M10_FLASH_IO3_HD_N: EUB1.7 RB35.2(B) RB100.1
SPI_M10_FLASH_IO3_HD_R_N: RB100.2(B) UT4.B9
SPI_M10_FLASH_MISO: EUB1.2 RB115.1 TP5.1(TP)
SPI_M10_FLASH_MISO_R: RB115.2(B) UT4.B6
SPI_M10_FLASH_MOSI: EUB1.5 RB118.1 TP6.1(TP)
SPI_M10_FLASH_MOSI_R: RB118.2(B) UT4.B5
SPI_PCH_SNIFF_CLK: JT3.208 UT4.A13
SPI_PCH_SNIFF_CS0_N: JT3.198 UT4.C13
SPI_PCH_SNIFF_CS1_N: JT3.210 UT4.E10
SPI_PCH_SNIFF_IO0: JT3.200 UT4.A14
SPI_PCH_SNIFF_IO1: JT3.202 UT4.B13
SPI_PCH_SNIFF_IO2: JT3.204 UT4.C12
SPI_PCH_SNIFF_IO3: JT3.206 UT4.D12
TP_BMC_RMII_MDC: JT3.218
TP_BMC_RMII_MDIO: JT3.214
TP_BMC_RTCK: JT3.168
TP_C5_DNU_0: UT7.E12
TP_C5_DNU_1: UT7.D23
TP_C5_DNU_2: UT7.AE14
TP_C5_DNU_3: UT7.U8
TP_C5_DNU_4: UT7.B2
TP_C5_DNU_5: UT7.A2
TP_C5_FPGA_AS_DATA1: UT7.AC6
TP_C5_FPGA_AS_DATA2: UT7.AC5
TP_C5_FPGA_AS_DATA3: UT7.AB6
TP_C5_FPGA_AS_NCSO: UT7.AA6
TP_C5_GPIO4A_IO20: UT7.AE22
TP_C5_GPIO4A_IO22: UT7.AG21
TP_C5_GPIO4A_IO24: UT7.AF20
TP_C5_GPIO4A_IO26: UT7.AE20
TP_C5_GPIO4A_IO41: UT7.AD17
TP_C5_GPIO4A_IO43: UT7.AE17
TP_C5_GPIO4A_IO45: UT7.AG14
TP_C5_Y16: UT7.Y16
TP_DEDI_VPPACC: TP7.1(TP)
TP_EMMC_STRB: RT14.2(B)
TP_FAN_TACH6: JT3.90
TP_FAN_TACH7: JT3.92
TP_GXB_TX_L1_DN: UT7.Y1
TP_GXB_TX_L1_DP: UT7.Y2
TP_GXB_TX_L2_DN: UT7.T1
TP_GXB_TX_L2_DP: UT7.T2
TP_GXB_TX_L3_DN: UT7.M1
TP_GXB_TX_L3_DP: UT7.M2
TP_GXB_TX_L4_DN: UT7.H1
TP_GXB_TX_L4_DP: UT7.H2
TP_GXB_TX_L5_DN: UT7.D1
TP_GXB_TX_L5_DP: UT7.D2
TP_HPS_GPI0: UT7.M25
TP_HPS_GPI1: UT7.K27
TP_HPS_GPI2: UT7.R20
TP_HPS_GPI3: UT7.R21
TP_HPS_GPI4: UT7.R28
TP_HPS_GPI5: UT7.P26
TP_HPS_GPI6: UT7.T17
TP_HPS_GPI7: UT7.T16
TP_HPS_GPI8: UT7.Y28
TP_HPS_GPI9: UT7.Y26
TP_HPS_GPI10: UT7.U15
TP_HPS_GPI11: UT7.U16
TP_HPS_GPI12: UT7.AC27
TP_HPS_GPI13: UT7.V24
TP_IRQ_SMB_TMPSNSR_ALERT_R342_N: UT10.3
TP_M10_A7: UT4.A7
TP_M10_C14: UT4.C14
TP_M10_CRC_ERROR: UT4.C5
TP_M10_DEV_OE: UT4.B8
TP_M10_IO2_J6: UT4.J6
TP_M10_IO4_P10: UT4.P10
TP_M10_IO4_P11: UT4.P11
TP_M10_IO4_P12: UT4.P12
TP_M10_IO4_P13: UT4.P13
TP_M10_J12: UT4.J12
TP_M10_R15: UT4.R15
TP_M10_VREFB1: UT4.J1
TP_M10_VREFB2: UT4.M1
TP_M10_VREFB3: UT4.T7
TP_M10_VREFB4: UT4.T13
TP_M10_VREFB5: UT4.R16
TP_M10_VREFB6: UT4.B15
TP_MAX_CLKOUT: EUT3.28
TP_MAX_FAN_FAIL_N: EUT3.24
TP_OCP_BMC_RMIIRXER: JT3.222
TP_RST_BMC_CPU_N: JT3.253
TP_RST_RSTB_BMC_R_N: JT3.113
TP_SPI_BMC_BOOT_CLK: JT3.73
TP_SPI_BMC_BOOT_CS0_N: JT3.63
TP_SPI_BMC_BOOT_CS1: JT3.75
TP_SPI_BMC_BOOT_DI_R1: JT3.67
TP_SPI_BMC_BOOT_DO: JT3.65
TP_SPI_BMC_BOOT_IO2: JT3.69
TP_SPI_BMC_BOOT_IO3: JT3.71
TP_TRC_HPS_TRACE32_D4: UT7.A20
TP_TRC_HPS_TRACE32_D5: UT7.J18
TP_TRC_HPS_TRACE32_D6: UT7.A19
TP_TRC_HPS_TRACE32_D7: UT7.C18
TP_USB2B_PWREN: R412.2(B)
TP_V_M_BMC_DDR3_CKE1: UT7.K28
TP_V_M_BMC_DDR3_CS1_N: UT7.L20
TP_V_M_BMC_DDR3_ODT1: UT7.G26
TP_V_M_CE1: U2.J9
TP_V_M_CE1_1: U3.J9
TP_V_M_CE1_2: U4.J9
TP_V_M_CS1_1_N: U3.L1
TP_V_M_CS1_2_N: U4.L1
TP_V_M_CS1_N: U2.L1
TP_V_M_ODT1: U2.J1
TP_V_M_ODT1_1: U3.J1
TP_V_M_ODT1_2: U4.J1
TP_V_M_ZQ1: U2.L9
TP_V_M_ZQ1_1: U3.L9
TP_V_M_ZQ1_2: U4.L9
TP_VCC_RGMII_REF: JT3.2
TP_VR_P1V15_AUX_BMC_EN: JT3.61
TRC_HPS_TRACE32_D0: RT8.2(B) UT7.A22
TRC_HPS_TRACE32_D0_R: J4.14 RT8.1
TRC_HPS_TRACE32_D1: RT7.2(B) UT7.B21
TRC_HPS_TRACE32_D1_R: J4.16 RT7.1
TRC_HPS_TRACE32_D2: RT6.2(B) UT7.A21
TRC_HPS_TRACE32_D2_R: J4.18 RT6.1
TRC_HPS_TRACE32_D3: RT2.2(B) UT7.K18
TRC_HPS_TRACE32_D3_R: J4.20 RT2.1
TRC_TRACE32_CLK: RT9.2(B) UT7.C21
TRC_TRACE32_CLK_R: J4.12 RT9.1
ULPI_USBPHY_PCH_CLKOUT: R8A57.2(B) UT7.G4
ULPI_USBPHY_PCH_CLKOUT_R: R8A57.1 U8A6.1
ULPI_USBPHY_PCH_DATA<0>: R8A55.2(B) UT7.C10
ULPI_USBPHY_PCH_DATA<1>: R8A53.2(B) UT7.F5
ULPI_USBPHY_PCH_DATA<2>: R8A51.2(B) UT7.C9
ULPI_USBPHY_PCH_DATA<3>: R8A49.2(B) UT7.C4
ULPI_USBPHY_PCH_DATA<4>: R8A47.2(B) UT7.C8
ULPI_USBPHY_PCH_DATA<5>: R8A44.2(B) UT7.D4
ULPI_USBPHY_PCH_DATA<6>: R8A45.2(B) UT7.C7
ULPI_USBPHY_PCH_DATA<7>: R8A43.2(B) UT7.F4
ULPI_USBPHY_PCH_DIR: R8A61.2(B) UT7.E5
ULPI_USBPHY_PCH_DIR_R: R8A61.1 U8A6.31
ULPI_USBPHY_PCH_NXT: R8A56.2(B) UT7.D5
ULPI_USBPHY_PCH_NXT_R: R8A56.1 U8A6.2
ULPI_USBPHY_PCH_R_DATA<0>: R8A55.1 U8A6.3
ULPI_USBPHY_PCH_R_DATA<1>: R8A53.1 U8A6.4
ULPI_USBPHY_PCH_R_DATA<2>: R8A51.1 U8A6.5
ULPI_USBPHY_PCH_R_DATA<3>: R8A49.1 U8A6.6
ULPI_USBPHY_PCH_R_DATA<4>: R8A47.1 U8A6.7
ULPI_USBPHY_PCH_R_DATA<5>: R8A44.1 U8A6.9
ULPI_USBPHY_PCH_R_DATA<6>: R8A45.1 U8A6.10
ULPI_USBPHY_PCH_R_DATA<7>: R8A43.1 U8A6.13
ULPI_USBPHY_PCH_STP: R8A64.2(B) U8A6.29 UT7.C5
ULPI_USBPHY_USB2B_CLKOUT: R408.2(B) UT7.B12
ULPI_USBPHY_USB2B_CLKOUT_R: EU12.1 R408.1
ULPI_USBPHY_USB2B_DATA<0>: R406.2(B) UT7.D14
ULPI_USBPHY_USB2B_DATA<1>: R405.2(B) UT7.A5
ULPI_USBPHY_USB2B_DATA<2>: R404.2(B) UT7.C13
ULPI_USBPHY_USB2B_DATA<3>: R403.2(B) UT7.B6
ULPI_USBPHY_USB2B_DATA<4>: R402.2(B) UT7.H13
ULPI_USBPHY_USB2B_DATA<5>: R400.2(B) UT7.A4
ULPI_USBPHY_USB2B_DATA<6>: R401.2(B) UT7.H12
ULPI_USBPHY_USB2B_DATA<7>: R399.2(B) UT7.B4
ULPI_USBPHY_USB2B_DIR: R409.2(B) UT7.B11
ULPI_USBPHY_USB2B_DIR_R: EU12.31 R409.1
ULPI_USBPHY_USB2B_NXT: R407.2(B) UT7.B9
ULPI_USBPHY_USB2B_NXT_R: EU12.2 R407.1
ULPI_USBPHY_USB2B_R_DATA<0>: EU12.3 R406.1
ULPI_USBPHY_USB2B_R_DATA<1>: EU12.4 R405.1
ULPI_USBPHY_USB2B_R_DATA<2>: EU12.5 R404.1
ULPI_USBPHY_USB2B_R_DATA<3>: EU12.6 R403.1
ULPI_USBPHY_USB2B_R_DATA<4>: EU12.7 R402.1
ULPI_USBPHY_USB2B_R_DATA<5>: EU12.9 R400.1
ULPI_USBPHY_USB2B_R_DATA<6>: EU12.10 R401.1
ULPI_USBPHY_USB2B_R_DATA<7>: EU12.13 R399.1
ULPI_USBPHY_USB2B_STP: EU12.29 R410.2(B) UT7.B8
UNNAMED_60_MPM3632_I11_OUTSENSE: RT69.1 UT8.10
UNNAMED_60_MPM3632_I18_OUTSENSE: RB81.1 UT5.10
UNNAMED_61_MPM3833_I38_OUTS: RT66.1 UT6.3
USB2_PCH_SMC_DN: JT3.217 U8A6.19
USB2_PCH_SMC_DP: JT3.219 U8A6.18
USB2_USB2B_DN: EU12.19 JT3.223
USB2_USB2B_DP: EU12.18 JT3.225
V_BMC_DAC_IOB: JT3.12 R417.2(B) R420.2(B) R423.2(B) R424.2(B) R429.1
V_BMC_DAC_IOG: JT3.10 R419.2(B) R422.2(B) R427.2(B) R428.2(B) R431.1
V_BMC_DAC_IOR: JT3.14 R418.2(B) R421.2(B) R425.2(B) R426.2(B) R430.1
V_BMC_DDC_SCL: JT3.20 R433.2(B) UT7.W24
V_BMC_DDC_SDA: JT3.22 R432.2(B) UT7.AB25
V_BMC_HSYN: JT3.16 R415.2(B)
V_BMC_HSYN_R: R415.1 UT7.E11
V_BMC_VSYN: JT3.18 R416.2(B)
V_BMC_VSYN_R: R416.1 UT7.D11
V_M_BMC_DDR3_BA0: RB6.1 U2.M2 U3.M2 U4.M2 UT7.A27
V_M_BMC_DDR3_BA1: RB11.1 U2.N8 U3.N8 U4.N8 UT7.H25
V_M_BMC_DDR3_BA2: RB5.1 U2.M3 U3.M3 U4.M3 UT7.G25
V_M_BMC_DDR3_CAS_N: RB40.1 U2.K3 U3.K3 U4.K3 UT7.A26
V_M_BMC_DDR3_CKE: RB19.1 RB20.1 U2.K9 U3.K9 U4.K9 UT7.L28
V_M_BMC_DDR3_CLK_DN: RB47.2(B) U2.K7 U3.K7 U4.K7 UT7.N20
V_M_BMC_DDR3_CLK_DP: RB47.1 U2.J7 U3.J7 U4.J7 UT7.N21
V_M_BMC_DDR3_CS_N: RB39.1 U2.L2 U3.L2 U4.L2 UT7.L21
V_M_BMC_DDR3_DM_0: U2.E7 UT7.G28
V_M_BMC_DDR3_DM_1: U2.D3 UT7.P28
V_M_BMC_DDR3_DM_2: U3.E7 UT7.W28
V_M_BMC_DDR3_DM_3: U3.D3 UT7.AB28
V_M_BMC_DDR3_DM_4: U4.E7 UT7.AE28
V_M_BMC_DDR3_DQ<0>: U2.E3 UT7.J25
V_M_BMC_DDR3_DQ<1>: U2.F7 UT7.J24
V_M_BMC_DDR3_DQ<2>: U2.F2 UT7.E28
V_M_BMC_DDR3_DQ<3>: U2.F8 UT7.D27
V_M_BMC_DDR3_DQ<4>: U2.H3 UT7.J26
V_M_BMC_DDR3_DQ<5>: U2.H8 UT7.K26
V_M_BMC_DDR3_DQ<6>: U2.G2 UT7.G27
V_M_BMC_DDR3_DQ<7>: U2.H7 UT7.F28
V_M_BMC_DDR3_DQ<8>: U2.D7 UT7.K25
V_M_BMC_DDR3_DQ<9>: U2.C3 UT7.L25
V_M_BMC_DDR3_DQ<10>: U2.C8 UT7.J27
V_M_BMC_DDR3_DQ<11>: U2.C2 UT7.J28
V_M_BMC_DDR3_DQ<12>: U2.A7 UT7.M27
V_M_BMC_DDR3_DQ<13>: U2.A2 UT7.M26
V_M_BMC_DDR3_DQ<14>: U2.B8 UT7.M28
V_M_BMC_DDR3_DQ<15>: U2.A3 UT7.N28
V_M_BMC_DDR3_DQ<16>: U3.E3 UT7.N24
V_M_BMC_DDR3_DQ<17>: U3.F7 UT7.N25
V_M_BMC_DDR3_DQ<18>: U3.F2 UT7.T28
V_M_BMC_DDR3_DQ<19>: U3.F8 UT7.U28
V_M_BMC_DDR3_DQ<20>: U3.H3 UT7.N26
V_M_BMC_DDR3_DQ<21>: U3.H8 UT7.N27
V_M_BMC_DDR3_DQ<22>: U3.G2 UT7.R27
V_M_BMC_DDR3_DQ<23>: U3.H7 UT7.V27
V_M_BMC_DDR3_DQ<24>: U3.D7 UT7.R26
V_M_BMC_DDR3_DQ<25>: U3.C3 UT7.R25
V_M_BMC_DDR3_DQ<26>: U3.C8 UT7.AA28
V_M_BMC_DDR3_DQ<27>: U3.C2 UT7.W26
V_M_BMC_DDR3_DQ<28>: U3.A7 UT7.R24
V_M_BMC_DDR3_DQ<29>: U3.A2 UT7.T24
V_M_BMC_DDR3_DQ<30>: U3.B8 UT7.Y27
V_M_BMC_DDR3_DQ<31>: U3.A3 UT7.AA27
V_M_BMC_DDR3_DQ<32>: U4.E3 UT7.T26
V_M_BMC_DDR3_DQ<33>: U4.F7 UT7.U25
V_M_BMC_DDR3_DQ<34>: U4.F2 UT7.AC28
V_M_BMC_DDR3_DQ<35>: U4.F8 UT7.V25
V_M_BMC_DDR3_DQ<36>: U4.H3 UT7.V19
V_M_BMC_DDR3_DQ<37>: U4.H8 UT7.V20
V_M_BMC_DDR3_DQ<38>: U4.G2 UT7.AE27
V_M_BMC_DDR3_DQ<39>: U4.H7 UT7.AD28
V_M_BMC_DDR3_DQS0_N: U2.G3 UT7.R16
V_M_BMC_DDR3_DQS0_P: U2.F3 UT7.R17
V_M_BMC_DDR3_DQS1_N: U2.B7 UT7.R18
V_M_BMC_DDR3_DQS1_P: U2.C7 UT7.R19
V_M_BMC_DDR3_DQS2_N: U3.G3 UT7.T18
V_M_BMC_DDR3_DQS2_P: U3.F3 UT7.T19
V_M_BMC_DDR3_DQS3_N: U3.B7 UT7.T20
V_M_BMC_DDR3_DQS3_P: U3.C7 UT7.U19
V_M_BMC_DDR3_DQS4_N: U4.G3 UT7.V17
V_M_BMC_DDR3_DQS4_P: U4.F3 UT7.V18
V_M_BMC_DDR3_MA<0>: RB4.1 U2.N3 U3.N3 U4.N3 UT7.C28
V_M_BMC_DDR3_MA<1>: RB12.1 U2.P7 U3.P7 U4.P7 UT7.B28
V_M_BMC_DDR3_MA<2>: RB3.1 U2.P3 U3.P3 U4.P3 UT7.E26
V_M_BMC_DDR3_MA<3>: RB37.1 U2.N2 U3.N2 U4.N2 UT7.D26
V_M_BMC_DDR3_MA<4>: RB17.1 U2.P8 U3.P8 U4.P8 UT7.J21
V_M_BMC_DDR3_MA<5>: RB32.1 U2.P2 U3.P2 U4.P2 UT7.J20
V_M_BMC_DDR3_MA<6>: RB16.1 U2.R8 U3.R8 U4.R8 UT7.C26
V_M_BMC_DDR3_MA<7>: RB30.1 U2.R2 U3.R2 U4.R2 UT7.B26
V_M_BMC_DDR3_MA<8>: RB15.1 U2.T8 U3.T8 U4.T8 UT7.F26
V_M_BMC_DDR3_MA<9>: RB1.1 U2.R3 U3.R3 U4.R3 UT7.F25
V_M_BMC_DDR3_MA<10>: RB8.1 U2.L7 U3.L7 U4.L7 UT7.A24
V_M_BMC_DDR3_MA<11>: RB14.1 U2.R7 U3.R7 U4.R7 UT7.B24
V_M_BMC_DDR3_MA<12>: RB10.1 U2.N7 U3.N7 U4.N7 UT7.D24
V_M_BMC_DDR3_MA<13>: RB2.1 U2.T3 U3.T3 U4.T3 UT7.C24
V_M_BMC_DDR3_MA<14>: RB13.1 U2.T7 U3.T7 U4.T7 UT7.G23
V_M_BMC_DDR3_MA<15>: RB9.1 U2.M7 U3.M7 U4.M7 UT7.F24
V_M_BMC_DDR3_ODT: RB41.1 U2.K1 U3.K1 U4.K1 UT7.D28
V_M_BMC_DDR3_RAS_N: RB42.1 U2.J3 U3.J3 U4.J3 UT7.A25
V_M_BMC_DDR3_RST_N: RB23.1 U2.T2 U3.T2 U4.T2 UT7.V28
V_M_BMC_DDR3_WE_N: RB7.1 U2.L3 U3.L3 U4.L3 UT7.E25
V_M_BMC_DDR3_ZQ_0: RB44.1 U2.L8(ZQ)
V_M_BMC_DDR3_ZQ_1: RB43.1 U3.L8(ZQ)
V_M_BMC_DDR3_ZQ_2: RB45.1 U4.L8(ZQ)
VR_FET_SW_P3V3_AUX_P1V1_AUX: CB115.1 CB144.1 CB147.1 FBB5.2(B) UT6.13 UT6.14(VIN<1>)
VR_FET_SW_P3V3_AUX_P1V2_AUX: C107.1 CB173.1 FBB9.2(B) UT9.1(VIN)
VR_FET_SW_P3V3_AUX_P1V8_AUX: C114.1 CB184.1 FBB10.2(B) UT11.1(VIN)
VR_FET_SW_P12V_AUX_P1V5_AUX: CB112.1 CB127.1 CB131.1 FBB7.2(B) UT5.17 UT5.18(VIN<1>)
VR_FET_SW_P12V_AUX_P2V5_AUX: CB166.1 CB169.1 CB182.1 FBB11.2(B) UT8.17 UT8.18(VIN<1>)
VR_P0V75_AUX_REFIN: C8F4.1 EU8F1.1 R8F3.2(B) R8F5.1
VR_P0V75_AUX_SENSE: EU8F1.5(VOSNS) R8F1.1
VR_P0V75_AUX_VIN: C8F5.1 EU8F1.10 R8F6.2(B)
VR_P1V1_AUX_EN: RT67.2(B) UT6.4
VR_P1V1_AUX_FB: RT64.1 RT65.2(B) UT6.2
VR_P1V1_AUX_FB_R: RB113.2(B) RT65.1
VR_P1V2_AUX_EN: RB128.2(B) UT9.5
VR_P1V2_AUX_FB: RB121.1 RB124.2(B) UT9.9
VR_P1V2_AUX_FB_R: RB124.1 RB129.2(B)
VR_P1V5_AUX_EN: RT51.2(B) UT5.11
VR_P1V5_AUX_FB: RB80.1 RB93.2(B) UT5.13
VR_P1V5_AUX_FB_R: RB92.2(B) RB93.1
VR_P1V8_AUX_EN: RB141.2(B) UT11.5
VR_P1V8_AUX_FB: RB155.1 RB156.2(B) UT11.9
VR_P1V8_AUX_FB_R: RB156.1 RB157.2(B)
VR_P2V5_AUX_EN: RT62.2(B) UT8.11
VR_P2V5_AUX_FB: RB114.1 RB117.2(B) UT8.13
VR_P2V5_AUX_FB_R: RB117.1 RB120.2(B)
XTAL_SI5351_XA: C5C5.1 EU5C1.1 R5C3.1 YT1.1
XTAL_SI5351_XB: C5C6.1 EU5C1.2(XB) R5C3.2(B) YT1.3(B)
XTAL_USBPHY_PCH_24M_IN: C7A17.1 R7A57.1 U8A6.26 Y7A1.1
XTAL_USBPHY_PCH_24M_OUT: C7A16.1 R7A57.2(B) U8A6.25(XO) Y7A1.3(B)
XTAL_USBPHY_USB2B_24M_IN: C307.1 EU12.26 R398.1 Y2.1
XTAL_USBPHY_USB2B_24M_OUT: C306.1 EU12.25(XO) R398.2(B) Y2.3(B)

Pads without a net: EU5C1 15 16 17 19; EUT1 10 11 12 13 14 15 16 17; EUT2 8 9 12 13; QT1 1 2 6; UT4 B16 C6 C9 C10 C15 C16 D9 D14 D15 D16 E9 E14 E15 E16 F9 F14 F16 G11 G12 G14 G15 G16 H6 H11 H12 J2 J3 J5 J15 J16 L7 L8 M6 M7 M8 M9 M16 N1 N2 N3 N4 N5 P1 P2 P4 P5 P6 P8 P9 P16 R1 R2 R3 R4 R5 R6 R7 R8 R9 R10 R14 T2 T3 T4 T5 T6 T8 T9 T11 T14 T15; UT5 3 4 5 6 16; UT6 7 11 15; UT7 AA11 AC4 AD4 AD5 AE6 U10 V10 Y11; UT8 3 4 5 6 16; UT9 4; UT11 4

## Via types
v1: diameter 0.406, hole 0.203, TOP to BOTTOM, 1922 vias
v2: diameter 0.508, hole 0.254, TOP to BOTTOM, 76 vias

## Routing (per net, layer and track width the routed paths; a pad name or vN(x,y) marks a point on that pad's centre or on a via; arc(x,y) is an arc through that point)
AGND_ADC: length 20.8
  TOP w0.104: CT22.2 66.6,25.08 CT21.2 66.55,25.63 CT20.2 67.23,25.66 67.33,25.56 v1(67.4,25.56)
  TOP w0.254: CT17.2 CT16.2 v1(67.25,28.35) ; v1(63.38,29.45) 62.94,29.02 UT4.E2 ; CT19.2 CT18.2 v1(67.3,27.08) ; UT4.D2 63.39,27.51 v1(63.42,27.51) ; UT4.F3 62.01,30.02 v1(62.56,29.47) ; CT15.2 CT13.2 v1(67.25,29.75) ; CT12.2 CT11.2 66.87,30.89 67.09,31.11 v1(67.31,31.11)
  BOTTOM w0.112: CB160.2 67.19,29.69 v1(67.25,29.75)
  BOTTOM w0.254: v1(63.42,27.51) 62.96,27.51 62.5,27.97 61.11,27.97 60.86,28.21 CB122.2 60.09,28.21 CB121.2 ; CB103.2 67.15,30.41 67.18,30.38 v1(67.23,30.38) ; CB116.2 62.16,29.07 v1(62.56,29.47) ; FBB6.1 66.8,26.5 67.25,26.95 67.25,27.03 v1(67.3,27.08) ; CB91.2 66.76,31.15 CB96.2 67.3,31.12 v1(67.31,31.11) ; CB124.2 64.98,27.87 64.85,27.74 64.85,27.53 ; 64.85,27.53 63.77,26.45 CB143.2 ; 64.85,27.53 v1(64.79,27.53) ; CB120.2 62.86,28.94 v1(63.38,29.45)
GND: length 605.6
  TOP w0.089: UT7.R1 v1(29.98,8.81)
  TOP w0.127: UT7.N8 v1(27.58,13.61) ; UT7.P8 v1(28.38,13.61)
  TOP w0.254: UT4.J10 v1(54.38,33.52) ; U4.B9 v1(36.15,34.36) ; v1(24.41,8.01) 24.78,8.38 UT7.J1 UT7.K1 ; v1(18.8,29.61) 18.8,29.59 UT7.B27 ; UT4.E13 v1(51.38,28.52) ; UT7.V9 v1(32.38,14.41) ; U3.P1 v1(33.57,44.81) ; v1(51.25,3.31) 51.25,3.15 50.93,2.83 JT3.191 ; JT3.33 9.43,2.96 9.14,3.25 v1(9.14,3.51) ; UT4.E6 v1(59.38,28.52) ; UT7.AD6 v1(37.18,12.01) UT7.AE5 ; UT7.AG3 v1(38.78,9.61) UT7.AF3 ; v1(64.66,24.75) 64.64,24.77 64.13,24.77 UT4.A1 ; v2(10.51,20.6) 10.77,20.86 UT6.16 11.82,20.71 UT6.1 ; U4.E2 v1(42.52,37.54) ; UT7.B5 v1(18.78,11.21) ; U3.B9 v1(26.37,34.4) ; UT7.D19 v1(20.38,23.21) ; U2.B1 v1(23.73,34.43) ; UT7.E24 v1(21.18,26.41) UT7.E23 ; v2(3.27,17.43) 3.4,17.3 3.99,17.3 UT8.14 ; UT7.V26 32.38,28.81 v1(32.4,28.81) ; UT7.AF16 v1(38.78,20.81) ; J4.15 5.27,48.72 v1(5.84,49.28) ; UT7.W18 v1(33.18,22.41) ; v1(34,28.01) 33.98,28.01 UT7.Y25 ; UT7.AD25 v1(37.18,28.01) ; UT7.L9 v1(25.98,14.41) ; v1(52.42,17.43) 52.42,18.69 R429.2 ; v1(17.91,15.12) 17.91,15.14 UT7.A10 ; v1(2.05,38.87) 3.47,38.87 3.75,39.14 S7A2.1 2.87,39.5 2.64,39.73 v1(2.05,39.73) ; v1(62.71,15.3) 62.27,14.86 Y7A1.2 62.23,14.41 C7A17.2 ; UT7.U20 31.55,23.98 31.55,23.98 v1(31.58,24.01) ; v1(39.49,3.16) 39.49,3.15 39.49,3.1 39.43,3.04 JT3.145 ; U4.B1 v1(43.35,34.36) ; RT42.2 66.43,33.3 66.82,32.91 v1(66.82,32.26) ; RT1.2 v1(13.08,40.5) ; UT7.T3 v1(29.98,9.61) UT7.R3 ; JT3.11 3.93,3.29 v1(3.98,3.34) ; UT7.E9 v1(21.18,14.41) ; v1(6.93,45.78) 6.54,46.16 J4.13 ; JT3.185 49.38,1.63 49.38,3.08 v1(49.39,3.1) ; UT7.E6 v1(21.98,12.01) UT7.F6 ; v1(7.28,49.28) 7.33,49.23 7.56,49.23 7.81,48.98 J4.11 ; CT14.2 2,22.95 1.56,23.4 v2(1.56,24.1) ; UT7.AD22 v1(36.37,24.8) ; J8.2 50.26,49.15 50.23,49.18 v1(50.23,49.26) ; v2(13.68,8.67) 12.73,7.71 v2(12.73,7.65) ; CT4.2 12.81,36.65 v1(12.98,36.47) ; QT1.4 14.94,23.62 14.76,23.8 v1(14.36,23.8) ; U2.J2 v1(22.93,40.83) ; UT4.L14 v1(50.41,34.55) ; v1(20.4,5.75) 20.67,6.03 21.72,6.03 CT28.2 ; UT8.20 2.66,14.4 v2(2.63,14.38) 2.63,14.64 2.9,14.9 UT8.19 ; v1(59.61,12.58) 59.94,12.91 C7A16.2 ; UT4.N15 50.17,37.31 50.18,37.31 50.27,37.4 v1(50.38,37.4) ; U4.D8 v1(36.95,36.76) U4.E8 ; U4.T1 v1(43.35,46.36) ; UT7.M11 v1(26.78,16.01) ; JT3.251 65.93,2.96 66.04,3.07 v1(66.04,3.33) ; U2.T1 v1(23.73,46.43) ; UT7.R15 29.9,19.28 UT7.T14 v1(30.78,18.41) ; UT7.AA17 v1(34.78,21.61) ; C5C5.2 50.45,13.71 50.67,13.49 v1(50.67,13.16) ; UT7.E27 v1(21.18,29.61) ; UT7.H3 v1(23.58,9.61) ; U2.G1 v1(23.73,38.43) ; RT81.2 RT80.2 59.38,21.95 v1(59,21.57) ; RT130.2 42.11,4.98 42.36,4.73 42.82,4.73 v1(43.15,4.4) 43.1,4.4 42.77,4.4 42.44,4.07 42.44,1.58 JT3.157 ; JT3.245 64.43,2.96 64.56,3.1 v1(64.56,3.32) ; UT4.T1 63.88,40.59 v1(63.85,40.62) ; v1(62.33,21.61) RT75.2 RT83.2 ; UT4.F15 v1(49.4,29.54) ; 3.78,19.33 3.9,19.21 4.54,19.21 4.64,19.31 UT5.2 ; 3.78,19.33 v2(3.22,19.33) ; 3.78,19.33 4.24,19.8 UT5.1 ; RT91.1 57.88,14.93 57.44,15.37 v1(57.35,15.37) CT23.2 ; v1(24.38,8.81) UT7.J2 24.83,9.15 25.52,9.15 UT7.K2 ; U3.J2 v1(32.77,40.81) ; v1(16.53,38.43) U2.G9 U2.G8 ; UT4.K1 v1(64.38,34.52) ; JT3.151 40.93,3.04 40.86,3.1 40.86,3.15 v1(40.86,3.15) ; UT7.E1 v1(21.18,8.01) ; CT3.2 8.6,39.4 8.4,39.6 v1(8.4,39.62) ; U4.J8 v1(36.95,40.76) ; v1(12.55,3.34) 12.55,3.08 12.43,2.96 JT3.45 ; UT7.H4 v1(23.58,10.41) ; UT7.P16 v1(28.38,20.81) ; v1(60.67,7.6) 60.92,7.84 C3L11.2 ; UT7.AC26 v1(35.6,28.78) ; UT7.R11 v1(29.98,16.01) ; JT3.203 53.93,2.89 53.64,3.18 v1(53.64,3.24) ; UT7.F1 v1(21.98,8.01) ; UT7.F23 v1(21.98,26.41) ; UT7.B15 v1(18.78,20.01) ; v1(52.56,3.17) 52.5,3.11 52.5,1.64 JT3.197 ; UT7.L24 26,27.19 v1(26,27.21) ; UT7.N2 v1(28.38,8.81) UT7.P2 ; UT7.H18 v1(23.58,22.41) ; JT3.163 43.93,3.16 43.95,3.19 v1(43.95,3.2) ; UT7.N1 v1(28.38,8.01) UT7.P1 ; UT4.G10 v1(54.38,30.52) ; v1(62.33,34.47) 62.33,34.47 UT4.K3 ; U4.T9 v1(36.15,46.36) ; UT4.N12 v1(52.42,36.56) ; v2(10.79,17.3) 10.79,17.87 RT64.2 ; UT4.K7 v1(58.38,34.52) ; RT25.2 44.7,30.38 v1(44.72,30.41) ; JT3.233 61.43,2.96 61.54,3.07 v1(61.54,3.31) ; v1(46.86,6.69) 46.78,6.69 45.74,7.73 RT103.2 ; v1(36.98,39.19) U4.G9 U4.G8 ; UT7.J9 v1(24.38,14.41) ; UT7.B3 v1(18.78,9.61) UT7.A3 ; RT104.2 42.96,7 43.01,6.95 v1(43.1,6.95) ; UT7.AE1 v1(37.98,8.81) UT7.AE2 ; UT7.AB3 v1(35.58,9.61) ; UT7.U1 v1(31.58,8.81) UT7.V1 ; v2(12.73,7.65) 12.67,7.65 12.48,7.47 EUT3.7 ; v2(12.73,7.65) 12.48,7.4 EUT3.8 ; U4.F9 v1(36.15,37.56) ; UT4.H14 v1(50.36,31.5) ; YT1.4 49.33,14.93 v1(49.78,14.48) 50.17,14.88 C107.2 ; v1(27.58,21.58) 27.95,21.21 UT7.N17 ; v1(34.78,14.43) 34.76,14.43 UT7.AA9 ; UT7.E19 v1(21.18,23.21) ; v1(54.35,40.52) 54.85,40.02 UT4.T10 ; v1(46.4,18.24) 46.4,18.29 46.26,18.43 RT60.1 ; JT3.133 34.43,2.91 34.18,3.15 v1(34.18,3.16) ; UT7.AB2 v1(35.58,8.81) UT7.AB1 ; UT8.2 4.64,13.37 v2(4.77,13.24) 4.62,13.24 4.24,13.62 UT8.1 ; UT5.14 4.09,22.49 UT5.15 3.49,22.98 3.52,23.02 v2(3.52,23.4) ; UT7.H24 23.6,27.19 v1(23.58,27.19) ; U3.M9 v1(26.37,43.21) ; UT7.C1 v1(19.58,8.01) ; UT7.AE16 v1(37.98,20.81) ; UT7.K20 25.98,23.21 v1(26,23.21) 26,23.18 UT7.L19 ; U4.M9 v1(36.15,43.16) ; UT4.H7 v1(58.38,31.52) ; v1(66.9,13.09) 65.51,13.09 65.19,12.77 Y7A1.4 ; v1(45.54,16.74) 45.74,16.53 YT1.2 ; UT7.H11 v1(23.58,16.01) ; UT7.M16 v1(26.78,20.81) ; UT7.AD8 37.18,13.61 v1(37.18,13.59) ; JT1.8 v1(63.72,49.18) ; U2.D8 v1(18.13,36.03) ; JT3.57 15.43,2.81 15.54,2.92 15.54,3.21 v1(15.61,3.28) ; UT7.P20 v1(28.38,24.01) ; UT7.V21 32,24.41 32.36,24.77 v1(32.36,24.79) ; U3.T1 v1(33.57,46.41) ; v1(5.99,31.47) 6.42,31.91 CT8.2 ; UT7.J5 v1(24.38,11.21) UT7.H5 ; UT7.AF24 v1(38.78,27.21) ; UT7.Y3 v1(33.98,9.61) ; v1(7.98,36.47) 8.42,36.04 CT6.2 ; UT7.U3 v1(31.58,9.61) UT7.U2 ; U3.G8 27.54,38.77 26.8,38.77 U3.G9 v1(26.37,38.4) ; U4.J2 v1(42.55,40.76) ; UT7.Y20 v1(33.98,24.01) ; UT7.N13 v1(27.58,17.61) ; UT7.U17 v1(31.58,21.61) ; EUT1.9 13.81,14.89 v2(13.56,14.64) ; UT10.4 41.99,14.24 42.36,14.61 42.65,14.61 v1(42.71,14.66) ; U3.E2 v1(32.76,37.59) 33.15,37.2 U3.E1 ; v1(66.57,17.89) 66.57,17.91 66.58,17.92 Y2.4 ; UT7.P25 v1(28.38,28.01) ; JT3.39 10.93,2.99 10.55,3.37 v1(10.55,3.64) ; UT7.K16 v1(25.18,20.81) ; UT7.F3 v1(21.98,9.61) ; C322.2 67.85,16.49 C321.2 67.85,15.54 v1(67.81,15.5) ; CT10.2 13.19,28.27 v1(12.98,28.47) ; v1(55.39,37.52) 55.38,37.52 UT4.N9 ; UT7.G3 v1(22.78,9.61) ; v1(10,35.46) 9.37,36.09 CT5.2 ; UT7.AA2 v1(34.78,8.81) UT7.AA1 ; U4.P9 v1(36.15,44.76) ; UT7.M14 v1(26.78,18.41) ; UT7.N15 v1(27.58,20.01) ; v1(28.38,22.43) 28.78,22.03 UT7.P18 ; U3.M1 v1(33.57,43.21) ; v2(2.63,17.18) 2.74,17.18 3.02,16.9 UT8.15 ; UT5.19 3.24,20.49 2.97,20.22 2.89,20.22 v2(2.66,19.99) UT5.20 ; v1(10.98,30.47) 10.38,31.08 CT9.2 ; JT3.227 59.93,2.8 59.89,2.85 v1(59.89,3.13) ; v1(65.22,8.74) 64.64,8.16 64.32,8.16 CT24.2 ; U2.T9 v1(16.53,46.43) ; UT1.2 3.18,31.31 3.02,31.15 v1(2.64,31.15) ; v1(13.89,4.17) 13.89,3.55 14.12,3.32 14.12,2.94 13.93,2.75 JT3.51 ; UT7.AA3 v1(34.78,9.61) ; UT7.E22 v1(21.18,25.61) ; UT7.L8 v1(26.78,13.61) UT7.M8 ; UT4.D3 62.15,27.75 v1(62.15,27.54) ; v1(31.46,26.32) 31.46,26.52 UT7.U24 ; UT7.D21 v1(20.38,24.81) ; UT7.T10 v1(30.78,15.21) ; v1(26,29.61) 26,29.59 UT7.L27 ; v1(34.36,6.97) 34.26,6.86 RT123.1 ; v1(32.76,3.38) 32.93,3.22 JT3.127 ; UT7.H27 v1(23.58,29.61) ; UT7.P12 v1(28.38,16.81) ; UT7.N3 v1(27.58,9.61) UT7.M3 27.15,9.98 26.41,9.98 UT7.L3 UT7.L2 UT7.L1 v1(26.78,8.01) ; U2.M1 v1(23.73,43.23) ; UT7.E3 v1(21.18,9.61) ; UT7.AG1 v1(39.58,8.81) UT7.AG2 ; UT7.M10 v1(26.78,15.21) ; UT4.G8 v1(57.38,30.52) ; UT7.V3 v1(32.38,9.61) UT7.V2 ; UT7.P3 v1(28.38,9.61) ; U3.D1 v1(33.57,36) ; U3.T9 v1(26.37,46.41) ; UT7.K11 v1(25.18,16.81) UT7.K12 ; UT7.J3 v1(25.18,9.61) UT7.K3 ; UT7.B22 v1(18.78,25.61) ; v1(33.18,9.61) UT7.W3 v1(33.18,10.41) UT7.W4 ; U2.E8 v1(18.13,36.83) ; U2.D1 v1(23.73,36.03) ; UT7.W1 33.18,8.81 v1(33.18,8.81) UT7.W2 ; UT7.P5 v1(28.38,11.21) ; UT7.N4 v1(27.58,10.41) ; UT7.D13 v1(20.38,17.61) ; U3.E8 v1(27.17,36.8) ; UT7.C3 v1(19.58,9.61) ; UT7.P10 v1(28.38,15.21) ; R7A55.2 61.89,11.56 v1(62.29,11.56) ; UT9.10 53.03,16.43 52.98,16.48 52.98,16.57 v1(52.88,16.67) ; v1(56.66,3.31) 56.66,3.28 56.74,3.2 56.74,3.18 56.93,2.99 JT3.215 ; UT7.AB27 v1(35.57,29.6) ; UT7.AH20 v1(40.38,24.01) ; UT7.U12 v1(31.58,16.81) ; UT7.L17 26.35,21.21 v1(25.98,21.58) ; UT7.B25 18.8,27.99 v1(18.78,27.99) ; RB53.2 v1(57.58,44.35) ; UT7.AE18 v1(37.98,22.41) ; UT4.C11 53.46,26.6 v1(53.41,26.6) ; U2.B3 v1(22.13,34.43) ; U3.F9 v1(26.37,37.6) ; U2.F9 v1(16.53,37.63) ; UT4.K16 v1(48.38,34.02) ; UT4.M4 v1(61.38,36.52) ; v1(65.93,17.23) 65.7,17.23 65.36,17.57 C306.2 ; UT7.L10 v1(25.98,15.21) ; U4.P1 v1(43.35,44.76) ; C114.2 66.16,9.84 v1(66.16,9.2) ; U2.J8 v1(17.33,40.83) ; UT7.D10 v1(20.38,15.21) ; U4.B3 v1(41.75,34.36) ; UT7.H6 v1(23.58,12.01) ; UT4.T16 48.84,40.02 48.58,39.76 48.51,39.76 v1(48.42,39.66) ; JT3.139 35.93,2.78 v1(35.27,3.43) ; UT4.P3 v1(62.38,38.52) ; U2.A9 v1(16.53,33.63) ; UT7.AE3 v1(37.98,9.61) ; UT7.D3 v1(20.38,9.61) ; U3.B1 v1(33.57,34.4) ; UT7.AC1 v1(36.38,8.81) UT7.AC2 ; UT7.R2 v1(29.98,8.81) ; EUT2.7 6.75,10.77 v2(6.32,11.21) ; UT7.AG7 v1(39.58,12.81) ; UT7.B20 v1(18.78,24.01) ; UT7.H15 v1(23.58,20.01) ; U3.D8 v1(27.17,36) ; U2.E1 v1(23.73,36.83) ; UT7.L13 v1(25.98,17.61) ; U4.D1 v1(43.35,35.96) ; UT7.Y14 v1(33.98,18.41) ; U3.G1 v1(32.77,38.4) ; UT7.V14 v1(32.38,18.41) ; UT7.K14 v1(25.18,18.41) ; UT11.10 64.79,10.25 v1(65.18,9.86) ; JT3.221 58.5,1.64 58.5,3.03 v1(58.64,3.18) ; UT4.B14 v1(50.38,25.52) ; UT4.D6 v1(59.38,27.52) ; UT7.R8 v1(29.98,13.61) ; U3.A9 v1(26.37,33.6) ; UT7.AG17 v1(39.58,21.61) ; UT7.G1 v1(22.78,8.01) ; UT7.R13 v1(29.98,17.61) ; U2.P1 v1(23.73,44.83) ; UT7.Y12 v1(33.98,16.81) ; J4.3 v1(12.89,49.29) ; UT4.C8 v1(57.38,26.52) ; UT7.L5 v1(25.98,11.21) ; UT7.L15 v1(25.98,20.01) ; v1(47.62,12.73) 46.89,13.46 C5C6.2 ; UT7.K4 v1(25.18,10.41) ; v1(62.34,31.53) 62.34,31.48 UT4.G3 ; U2.E2 v1(22.93,36.83) ; RT85.2 v1(66.22,22.14) ; UT7.AG27 v1(39.58,29.61) ; UT7.U5 v1(31.58,11.21) ; UT4.A16 v1(48.38,24.52) ; U2.M9 v1(16.53,43.23) ; UT7.AD14 v1(37.18,18.41) ; UT7.AH10 v1(40.51,15.61) ; UT7.K8 v1(25.18,13.61) ; CB55.2 v1(58.21,44.4) ; UT7.AB24 v1(35.58,27.21) ; UT7.E2 v1(21.18,8.81) ; U2.B9 v1(16.53,34.43) ; UT7.V8 v1(32.38,13.61) ; R430.2 47.3,19.74 R431.2 47.3,18.42 v1(47.49,18.23) 47.58,18.23 ; JT3.9 3.43,3.27 v2(3.4,3.3) ; v1(62.83,3.05) 62.83,3.03 62.93,2.93 JT3.239 ; UT7.F2 v1(21.98,8.81) ; v1(44.49,11.59) 44.6,11.49 44.66,11.49 45.04,11.11 R5C14.2 R5C8.2 ; U4.A9 v1(36.15,33.56) ; U3.P9 v1(26.37,44.81) ; UT7.AA25 v1(34,27.23) ; UT7.D9 v1(20.38,14.41) ; UT4.P7 v1(58.38,38.52) ; UT7.U27 v1(31.54,29.57) ; U4.G1 v1(43.35,38.36) ; U3.B3 v1(31.96,35.19) ; UT7.M20 v1(26.78,24.01) ; UT7.G2 v1(22.78,8.81) ; UT7.H20 v1(23.58,24.01) ; U2.P9 v1(16.53,44.83) ; UT7.D16 v1(20.38,20.81) ; UT4.R13 v1(51.41,38.55) ; Y2.2 v1(64.48,21.11) ; UT7.N19 27.84,22.95 27.65,22.95 27.65,23.13 v1(27.58,23.21) ; UT4.K9 v1(55.38,34.52) ; C307.2 v1(67.1,21.34) ; J4.5 v1(11.62,49.29) ; U4.E1 v1(43.35,36.76) ; U3.J8 v1(27.17,40.81) ; UT7.W16 v1(33.18,20.81) ; UT7.C2 v1(19.58,8.81) ; UT7.B7 v1(18.78,12.81) ; UT7.AD3 v1(37.18,9.61) ; UT7.P9 v1(28.38,14.41) ; v1(55.34,49.26) J8.10 ; U4.M1 v1(43.35,43.16) ; UT7.C11 v1(20.38,16.01) ; UT7.AC3 v1(36.38,9.61) ; UT7.B17 v1(18.78,21.61) ; UT7.AF12 v1(38.78,16.81)
  TOP w0.508: v1(4.54,45.88) 4.54,45.91 4,46.44 J4.17 ; v1(16.53,37.63) 14.75,37.63 14.32,38.05 S7A1.1 16.06,38.89 v1(16.53,38.43) ; v2(2.03,45.62) 2.03,46.13 2.73,46.84 J4.19
  L9-GND w0.127: 32.89,17.23 33.39,17.23 33.42,17.25
  BOTTOM w0.089: v1(18.78,25.61) 17.89,25.61 17.62,25.88 ; v1(19.58,8.01) 19.22,7.65 ; 32.35,14.38 v1(32.38,14.41)
  BOTTOM w0.122: CB101.2 28.77,24.4 v1(28.38,24.01) 28.59,23.79 CB111.2
  BOTTOM w0.254: v1(48.42,39.66) 47.91,39.66 47.52,40.06 C8F2.2 ; CB128.2 28.83,22.37 28.44,22.37 v1(28.38,22.43) ; v1(23.58,29.61) 23.32,29.86 CB66.2 ; CB9.2 35.89,46.1 v1(36.15,46.36) ; CB193.2 28.3,11.28 v1(28.38,11.21) 28.53,11.21 CB192.2 ; v2(3.52,23.4) 3.78,23.14 CB127.2 ; CB19.2 16.53,43.23 v1(16.53,43.23) ; C310.2 C309.2 v1(61.23,17.86) ; CB27.2 32.35,40.39 v1(32.77,40.81) 33.24,40.34 CB26.2 ; U12.17 58.63,45.71 60.08,45.71 60.09,45.73 60.43,45.73 CB23.2 ; CB93.2 32.24,24.97 32.36,24.85 v1(32.36,24.79) 32.47,24.9 32.51,24.9 32.97,25.35 CB92.2 ; v1(36.98,39.19) 36.66,38.87 CB37.2 ; v1(62.21,9.98) 62.2,9.98 CB206.2 61.18,9.59 CB207.2 ; v1(26.37,43.21) 26.38,43.21 CB20.2 ; CB13.2 36.09,44.71 v1(36.15,44.76) ; v1(49.36,10.57) 49.61,10.32 CB199.2 ; v1(51.07,40.59) 51.28,40.39 CB51.2 ; C5C13.2 49.37,8.16 v1(49.24,8.29) 49.05,8.1 CB212.2 ; CB109.2 54.38,30.31 v1(54.38,30.52) 54.46,30.6 CB100.2 CB99.2 ; v1(55.34,49.26) 55.34,48.09 55.17,47.92 CB41.2 ; C8F3.2 C8F1.2 48.39,40.61 48.23,40.44 v1(48.23,40.16) ; CB167.2 25.49,16.49 v1(25.18,16.81) 24.86,16.49 CB168.2 ; v1(8.32,45.62) 8.32,45.26 8.07,45.01 Q3L1.4 ; v1(23.73,34.43) 23.83,34.53 CB52.2 ; v2(14.45,14.13) 14.45,14.12 14.45,13.56 RB137.2 RB136.2 ; CB4.2 23.86,46.29 v1(23.73,46.43) ; CB174.2 29.43,15.46 v1(29.98,16.01) 29.84,16.15 CB165.2 ; JT3.64 17.18,2.94 17.27,3.03 17.27,3.04 v1(17.32,3.1) ; v1(31.58,8.81) 31.53,8.76 CB211.2 ; JT3.232 61.18,2.82 61.37,3.01 61.37,3.01 61.54,3.18 v1(61.54,3.31) ; v1(54.35,40.52) 54.58,40.75 CB2.2 ; v1(25.98,20.01) 26.07,19.92 26.07,19.23 26.09,19.21 CB153.2 ; CB209.2 50.07,9.24 50.01,9.3 ; RB20.2 32.35,49.03 32.61,49.28 v1(32.76,49.28) ; CB86.2 62.77,33.3 CB83.2 CB78.2 ; v1(16.53,38.43) 16.55,38.41 CB34.2 ; CB94.2 27.08,25.82 26.96,25.95 CB87.2 26.96,26.24 26,27.2 v1(26,27.21) ; CB104.2 25.95,23.26 v1(26,23.21) ; RT78.2 17.64,21.01 17.31,20.68 17.31,20.59 17.04,20.33 16.96,20.33 16.85,20.22 ; v1(28.38,16.81) 28.48,16.91 CB159.2 ; v1(31.58,11.21) 31.07,11.71 CB191.2 ; v1(43.35,46.36) 43.44,46.27 CB5.2 ; v1(55.38,34.52) 54.94,34.96 54.17,34.96 53.99,35.13 CB65.2 ; CB110.2 49.43,29.54 v1(49.4,29.54) ; v1(15.61,3.28) 15.68,3.22 JT3.58 ; v1(59.18,23.86) 59.02,23.7 C312.2 C313.2 C314.2 C315.2 ; CB172.2 28.56,15.39 v1(28.38,15.21) ; v1(49.75,15.5) 50.17,15.08 CB173.2 ; CB144.2 11.4,19.53 CB147.2 v1(10.6,19.65) ; CB176.2 32.35,14.38 ; CB205.2 24.35,8.83 v1(24.38,8.81) ; JT3.238 62.68,2.82 62.83,2.98 v1(62.83,3.05) ; v1(25.98,11.21) 26.24,11.47 CB194.2 25.81,12.15 CB187.2 ; CB21.2 36.15,43.17 v1(36.15,43.16) ; CB11.2 43.36,44.75 v1(43.35,44.76) ; UB4.H9 v1(4.99,35.47) ; RB80.2 3.59,24.06 3.55,24.1 CB112.2 v2(1.56,24.1) ; v1(63.8,16.97) 63.86,16.91 C319.2 C320.2 65.61,16.91 v1(65.93,17.23) ; EU8F1.8 48.19,46.19 v1(48.16,46.22) 48.13,46.26 C8F8.2 ; CB50.2 26.34,34.44 v1(26.37,34.4) ; v1(37.18,13.59) 37.18,13.61 36.58,14.2 CB177.2 ; CB107.2 21.61,23.64 v1(21.18,23.21) ; v1(27.58,9.61) 27.36,9.39 CB203.2 ; CB46.2 23.87,35.88 v1(23.73,36.03) ; v1(43.38,32.64) 43.17,32.64 42.97,32.44 42.81,32.44 RB58.2 RB59.2 ; CB45.2 35.65,34.86 v1(36.15,34.36) ; UB4.G8 v1(5.99,36.47) 5.49,35.97 UB4.G9 ; CB73.2 32.61,28.59 v1(32.4,28.81) ; CB142.2 28.39,20.8 v1(28.38,20.81) ; v1(9.94,33.45) 9.49,33.9 UB4.J5 ; CB48.2 43.5,35.82 v1(43.35,35.96) ; CB123.2 36.42,22.65 CB105.2 35.76,23.64 v1(35.31,23.2) 35.31,23.13 34.88,22.7 CB106.2 ; CB64.2 55.39,37.52 v1(55.39,37.52) ; CB126.2 7.91,21.43 7.44,20.96 v2(7.31,20.96) ; v1(31.54,29.57) 31.78,29.81 CB68.2 ; v1(20.38,14.41) 20.41,14.37 CB181.2 ; CB148.2 30.05,19.13 v1(30.78,18.41) ; RB65.2 RB64.2 36.92,31.96 37.05,31.84 v1(37.05,31.8) ; CB81.2 44.56,27.77 v1(44.86,27.47) ; v1(30.78,15.21) 31.05,14.94 CB179.2 ; CB140.2 57.21,26.69 v1(57.38,26.52) 57.55,26.69 CB139.2 ; CB3.2 44.52,46.23 45.05,45.7 v1(45.13,45.7) ; 36.98,40.73 37.19,40.52 CB31.2 ; 36.98,40.73 RB45.2 ; 36.98,40.73 v1(36.95,40.76) ; CB184.2 64.61,14.05 v1(63.39,15.27) ; 45.4,23.56 v1(45.28,23.56) 45.28,23.5 45.57,23.21 R1A11.2 ; v1(42.87,25.33) 42.96,25.33 43.25,25.04 U7.2 ; CB200.2 25.51,9.94 v1(25.18,9.61) ; CB178.2 29.98,13.61 v1(29.98,13.61) ; CB129.2 51.61,28.29 v1(51.38,28.52) ; v1(28.38,14.41) 28.28,14.51 CB175.2 ; v1(59.61,12.58) 59.78,12.76 59.78,13.02 C2L34.2 60.22,13.05 60.62,12.64 C8A32.2 ; v1(56.38,36.45) 56.38,36.35 56.08,36.05 CB60.2 ; v1(23.73,43.23) 23.97,43.47 CB15.2 ; v1(58.38,38.52) 58.25,38.65 CB57.2 CB58.2 57.07,38.83 CB59.2 ; v1(28.52,3.1) 28.68,2.94 JT3.110 ; R397.2 64.79,20.8 v1(64.48,21.11) ; v1(56.66,3.31) 56.59,3.24 56.59,3.16 56.2,2.77 56.2,2.61 56.18,2.58 JT3.212 ; UB4.G7 v1(7.05,35.54) ; QB1.1 v1(66.82,32.26) ; CB98.2 58.15,31.28 v1(58.38,31.52) ; v1(26.37,44.81) 26.3,44.87 CB10.2 ; JT3.226 59.68,2.92 v1(59.89,3.13) ; v1(51.38,28.52) 51.64,28.78 CB118.2 ; v1(51.38,28.52) 51.18,28.72 CB119.2 ; UB3.2 53.08,41.88 53.36,41.6 v1(53.36,41.46) ; CB183.2 22.57,12.6 v1(21.98,12.01) 21.89,11.92 CB190.2 ; CB43.2 16.77,37.38 v1(16.53,37.63) ; v1(29.98,17.61) 29.91,17.67 CB157.2 ; JT3.52 14.18,2.96 14.15,2.98 14.15,3.45 13.89,3.71 v1(13.89,4.17) ; CB53.2 33.68,34.51 v1(33.57,34.4) ; CB201.2 47.4,10.13 v1(47.85,10.57) 48.04,10.76 R5C13.2 ; CB1.2 5.94,49.18 v1(5.84,49.28) ; v1(34.78,21.61) 34.83,21.56 CB132.2 35.81,21.56 CB134.2 ; v1(32.38,13.61) 32.77,13.21 32.96,13.21 32.99,13.19 33.24,13.19 33.32,13.11 RB135.2 33.74,12.87 34.13,12.48 CB188.2 CB189.2 ; CB136.2 53.68,26.6 v1(53.41,26.6) 53.3,26.6 53.21,26.69 CB141.2 ; v1(33.57,43.21) 33.82,43.45 CB16.2 ; v1(33.57,36) 33.72,35.86 CB47.2 ; EU8F1.4 47.69,43.79 EU8F1.11 v1(48.23,44.29) 48.62,44.29 48.89,44.02 50.72,44.02 C8F5.2 ; CB22.2 v1(58.67,49.21) ; v1(26.37,38.4) 26.39,38.38 CB35.2 ; v1(37.18,18.41) 36.97,18.2 CB156.2 ; R2A17.1 44.68,11.4 v1(44.49,11.59) ; CB161.2 27.02,16.25 v1(26.78,16.01) 26.51,16.28 CB162.2 ; CB196.2 23.86,11.73 v1(23.58,12.01) ; v1(26.78,24.01) 26.54,23.77 CB114.2 CB113.2 27.37,23.41 v1(27.58,23.21) ; v1(32.77,38.4) 33.58,38.4 33.71,38.27 CB39.2 ; CB146.2 CB145.2 15.92,19.45 16.16,19.69 16.16,19.69 16.57,20.1 CB152.2 16.85,20.22 ; v1(16.53,44.83) 16.42,44.73 CB12.2 ; v1(44.49,11.03) 44.49,10.78 43.91,10.19 CB204.2 ; UB1.2 12.94,49.19 12.89,49.24 v1(12.89,49.29) ; CB69.2 61.19,36.33 v1(61.38,36.52) 61.25,36.65 CB63.2 ; 52.91,37.96 52.91,38.32 CB17.2 ; 52.91,37.96 CB61.2 ; 52.91,37.96 52.83,38.04 52.1,38.04 51.91,37.85 CB62.2 v1(51.43,37.5) ; UB4.M4 v1(10.98,30.47) ; v1(67.3,27.77) FBB6.2 ; v1(27.58,20.01) 27.65,19.93 CB151.2 CB150.2 ; 16.85,20.22 v1(16.85,20.94) ; CB97.2 62.36,31.5 v1(62.34,31.53) 62.49,31.68 CB88.2 ; RB114.2 6.64,18.19 6.85,18.41 v2(6.85,18.93) ; JT3.126 32.68,3.3 v1(32.76,3.38) ; UB4.G2 v1(12.98,36.47) ; v1(5.61,28.4) 5.61,28.85 UB4.P9 ; v1(6.05,41.75) 6.05,43.71 Q3L1.1 ; CB90.2 22.56,25.82 v1(21.98,26.41) ; v1(63.34,34.5) 62.91,34.07 CB78.2 ; C9L13.2 44.32,48.02 44.57,48.28 v1(44.57,49.28) ; RB89.2 23.22,22.76 v1(23.58,22.41) ; CB71.2 58.32,34.58 v1(58.38,34.52) ; C2L18.2 55.33,8.54 v2(55.85,9.06) ; R411.1 v1(60.95,19.51) ; CB102.2 23.56,24.02 v1(23.58,24.01) ; v1(67.37,35.21) 67.91,35.21 TP2.1 ; v1(26.37,37.6) 26.15,37.38 CB42.2 ; v1(18.78,20.01) 19.45,19.33 CB149.2 ; CB195.2 24.59,11.42 v1(24.38,11.21) ; v1(59.38,28.52) 59.18,28.72 CB117.2 ; v1(35.6,28.78) 35.78,28.6 CB76.2 ; CT1.2 v1(56.06,42.13) ; CB137.2 61.88,27.02 62.15,27.29 v1(62.15,27.54) ; CB198.2 29.59,10 v1(29.98,9.61) ; CB115.2 11.11,23.84 11.3,23.65 v2(11.4,23.65) ; 50.01,9.3 v1(49.88,9.43) ; 50.01,9.3 C5N17.2 ; v1(47.49,18.23) 47.42,18.23 47.17,18.48 UB5.4 47.17,21.54 47.19,21.56 47.19,21.61 47.45,21.87 47.5,21.87 47.53,21.9 RB94.2 ; v2(3.4,3.3) 3.4,3.27 3.18,3.05 JT3.8 ; v1(51.07,41.57) 51.4,41.9 C8F4.2 51.4,42.68 R8F5.2 ; v1(24.41,8.01) 24.3,7.9 24.3,7.21 CB213.2 ; v1(43.35,34.36) 43.46,34.47 CB54.2 ; CB23.2 60.48,45.75 61,45.75 61.08,45.67 61.11,45.67 v1(61.16,45.62) ; CB23.2 CB33.2 ; 19.22,7.65 18.99,7.42 RB167.1 ; U8.3 26.18,7.54 26.31,7.54 v1(26.78,8.01) 26.44,8.35 CB208.2 ; C305.2 66.36,18.12 66.52,17.96 66.52,17.94 v1(66.57,17.89) ; JT3.114 29.61,1.64 29.61,3.03 v1(29.73,3.15) ; CB67.2 18.95,29.78 18.8,29.63 v1(18.8,29.61) ; v1(16.53,46.43) 16.22,46.12 CB8.2 ; UB4.G5 v1(10,35.46) ; CB158.2 20.5,17.73 v1(20.38,17.61) ; CB78.2 62.46,34.34 v1(62.33,34.47) 62.22,34.58 CB72.2 ; CB74.2 28.71,28.34 v1(28.38,28.01) ; C8F6.2 45.99,47.68 45.87,47.55 45.87,47.19 v1(45.81,47.14) ; CB180.2 26.52,13.35 v1(26.78,13.61) ; CB202.2 31.39,9.42 v1(31.58,9.61) ; v1(33.57,46.41) 33.71,46.27 CB6.2 ; v1(58.38,34.52) 58.69,34.21 CB82.2 ; v1(58.38,34.52) 58.2,34.33 CB79.2 ; v1(31.49,5.47) 31.49,5.52 31.12,5.89 RB187.2 30.96,6.06 30.68,6.34 RB180.2 ; CB18.2 v1(68.4,47.1) ; UB2.2 v1(53.08,45.62) ; CB75.2 50.87,33.06 CB85.2 50.83,32.74 50.84,32.73 50.84,32.61 50.85,32.6 50.85,32.39 50.86,32.39 CB89.2 50.37,31.5 v1(50.36,31.5) ; RB56.2 39.67,32.28 v1(39.67,31.8) ; C5C7.2 46.28,6.69 v1(46.86,6.69) 46.83,6.71 C5C2.2 ; C2L16.2 56.48,8.97 ; UB4.G6 v1(7.98,36.47) ; C1A7.2 39.59,47.61 40.04,47.16 v1(40.04,46.36) ; C5C1.2 47.59,8.54 v1(47.85,8.29) C5C8.2 ; RB68.2 65.98,36.53 v1(65.22,36.53) ; UB4.L3 v1(11.98,31.47) ; v1(54.38,33.52) 54.66,33.8 CB80.2 ; v1(34.18,3.16) 34.18,3.15 34.18,2.8 34.18,2.8 JT3.132 ; UB4.P2 v1(12.98,28.47) ; v1(25.98,21.58) 25.98,21.59 25.68,21.89 CB130.2 ; RT10.2 57.03,41.95 57.07,41.99 v1(57.19,41.99) ; v1(60.45,38.46) 60.25,38.65 CB56.2 ; RB48.2 58.11,49.13 v1(58.01,49.23) ; C308.2 v1(57.12,21.14) ; RB74.2 17.62,25.88 ; v1(58.82,19.39) 58.44,19.77 C317.2 ; CB84.2 31.04,26.94 31.46,26.52 v1(31.46,26.32) 31.11,25.96 30.37,25.96 30.03,25.62 CB95.2 ; RB132.2 12.05,14.37 v2(12.67,13.75) ; CB24.2 CB25.2 22.51,40.41 v1(22.93,40.83) ; CB40.2 43.48,38.23 v1(43.35,38.36) 43.74,38.75 CB32.2 ; CB44.2 35.92,37.34 v1(36.15,37.56) ; v1(52.42,36.56) 52.27,36.4 CB70.2 ; CB138.2 59.08,27.22 v1(59.38,27.52) 59.65,27.25 CB133.2 ; UB4.G4 v1(10.98,36.47) ; CB28.2 42.13,40.34 v1(42.55,40.76) ; C311.2 61.68,16.26 61.22,16.72 v1(61.18,16.72) C316.2 ; RB155.2 65.08,8.6 v1(65.22,8.74) ; C318.2 v1(58.72,17.79) ; C8F7.2 50.13,46.87 50.31,47.05 50.31,48.72 50.23,48.8 v1(50.23,49.26) ; UB4.G3 v1(11.98,36.47) ; v1(16.53,34.43) 16.92,34.82 CB49.2 ; CT7.2 v1(58.13,41.56) ; RB43.2 27.23,40.86 v1(27.17,40.81) 27.41,40.56 CB30.2 ; CB108.2 57.61,30.29 v1(57.38,30.52) 57.18,30.32 RB85.2 ; Q7A1.3 7.21,46.06 v1(6.93,45.78) ; CT2.2 CB36.2 v1(54.72,45.12) ; v1(40.86,31.88) 41.12,32.14 RB61.2 RB60.2 ; v1(38.02,31.88) RB62.2 RB63.2 ; CB38.2 23.86,38.29 v1(23.73,38.43) ; UB4.H2 v1(12.98,35.47) ; C1A8.2 36.54,47.89 36.8,47.63 36.92,47.63 37.75,46.8 38.04,46.8 v1(38.44,46.39) ; v1(18.78,27.99) 18.8,27.99 18.82,27.97 CB77.2 ; RB44.2 17.36,40.86 v1(17.33,40.83) 17.57,40.59 CB29.2 ; RB121.2 56.33,15.91 56.86,15.37 v1(57.35,15.37) ; CB135.2 37.69,21.1 v1(37.98,20.81) ; v1(64.95,35.17) 65.01,35.24 65.42,35.24 65.52,35.14 QB1.4 ; v1(26.37,46.41) 26.24,46.27 CB7.2 ; CB14.2 v1(68.47,47.94) ; C1A6.2 v1(44.34,40.77) ; JT3.24 7.18,3.05 7.21,3.08 v1(7.21,3.36) ; UB4.L8 v1(5.99,31.47) ; v2(9.62,20.48) 9.37,20.73 CB125.2 ; v1(6.9,31.43) 7.35,30.97 UB4.M7
  BOTTOM w0.381: CB154.2 33.94,18.45 v1(33.98,18.41) ; CB155.2 25.28,18.51 v1(25.18,18.41)
  BOTTOM w0.508: Q6A1.3 4.08,46 4.21,45.88 v1(4.54,45.88) ; CB131.2 6.9,21.37 v2(7.31,20.96)
  vias: v1(8.73,15.27) v1(9.37,15.27) v1(10,15.27) v1(47.85,9.43) v1(48.99,9.43) v1(56.1,31.53) v1(56.64,5.64) v1(56.89,7.17) v1(57.91,44.96) v1(59.2,7.12) v1(60.19,18.06) v1(60.55,6.99) v1(62.25,6.99) v1(62.78,40.82) v1(64.46,41.38) v2(4.79,11.08) v2(4.92,9.68) v2(5.56,10.44) v2(6.32,9.68) v2(12.67,15.52) v2(12.92,9.05) v2(13.68,7.65) v2(14.45,15.52) v2(14.7,9.05) v2(14.7,7.65) v2(55.85,10.32) v2(56.48,11.71) v2(57.24,11.71) v2(57.24,10.32) v2(57.24,9.05) v2(58.64,11.71) v2(58.64,10.32)
